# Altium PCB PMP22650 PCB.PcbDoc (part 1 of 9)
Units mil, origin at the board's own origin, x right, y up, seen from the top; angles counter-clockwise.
Board outline 11311 x 5233 mil, 8 copper layers (Layer 1, Layer 2, Layer 3, Layer 4, Layer 5, Layer 6, Layer 7, Layer 8), stack 88.6 mil thick; 633 components, 410 nets, 2503 pads, 1993 vias.
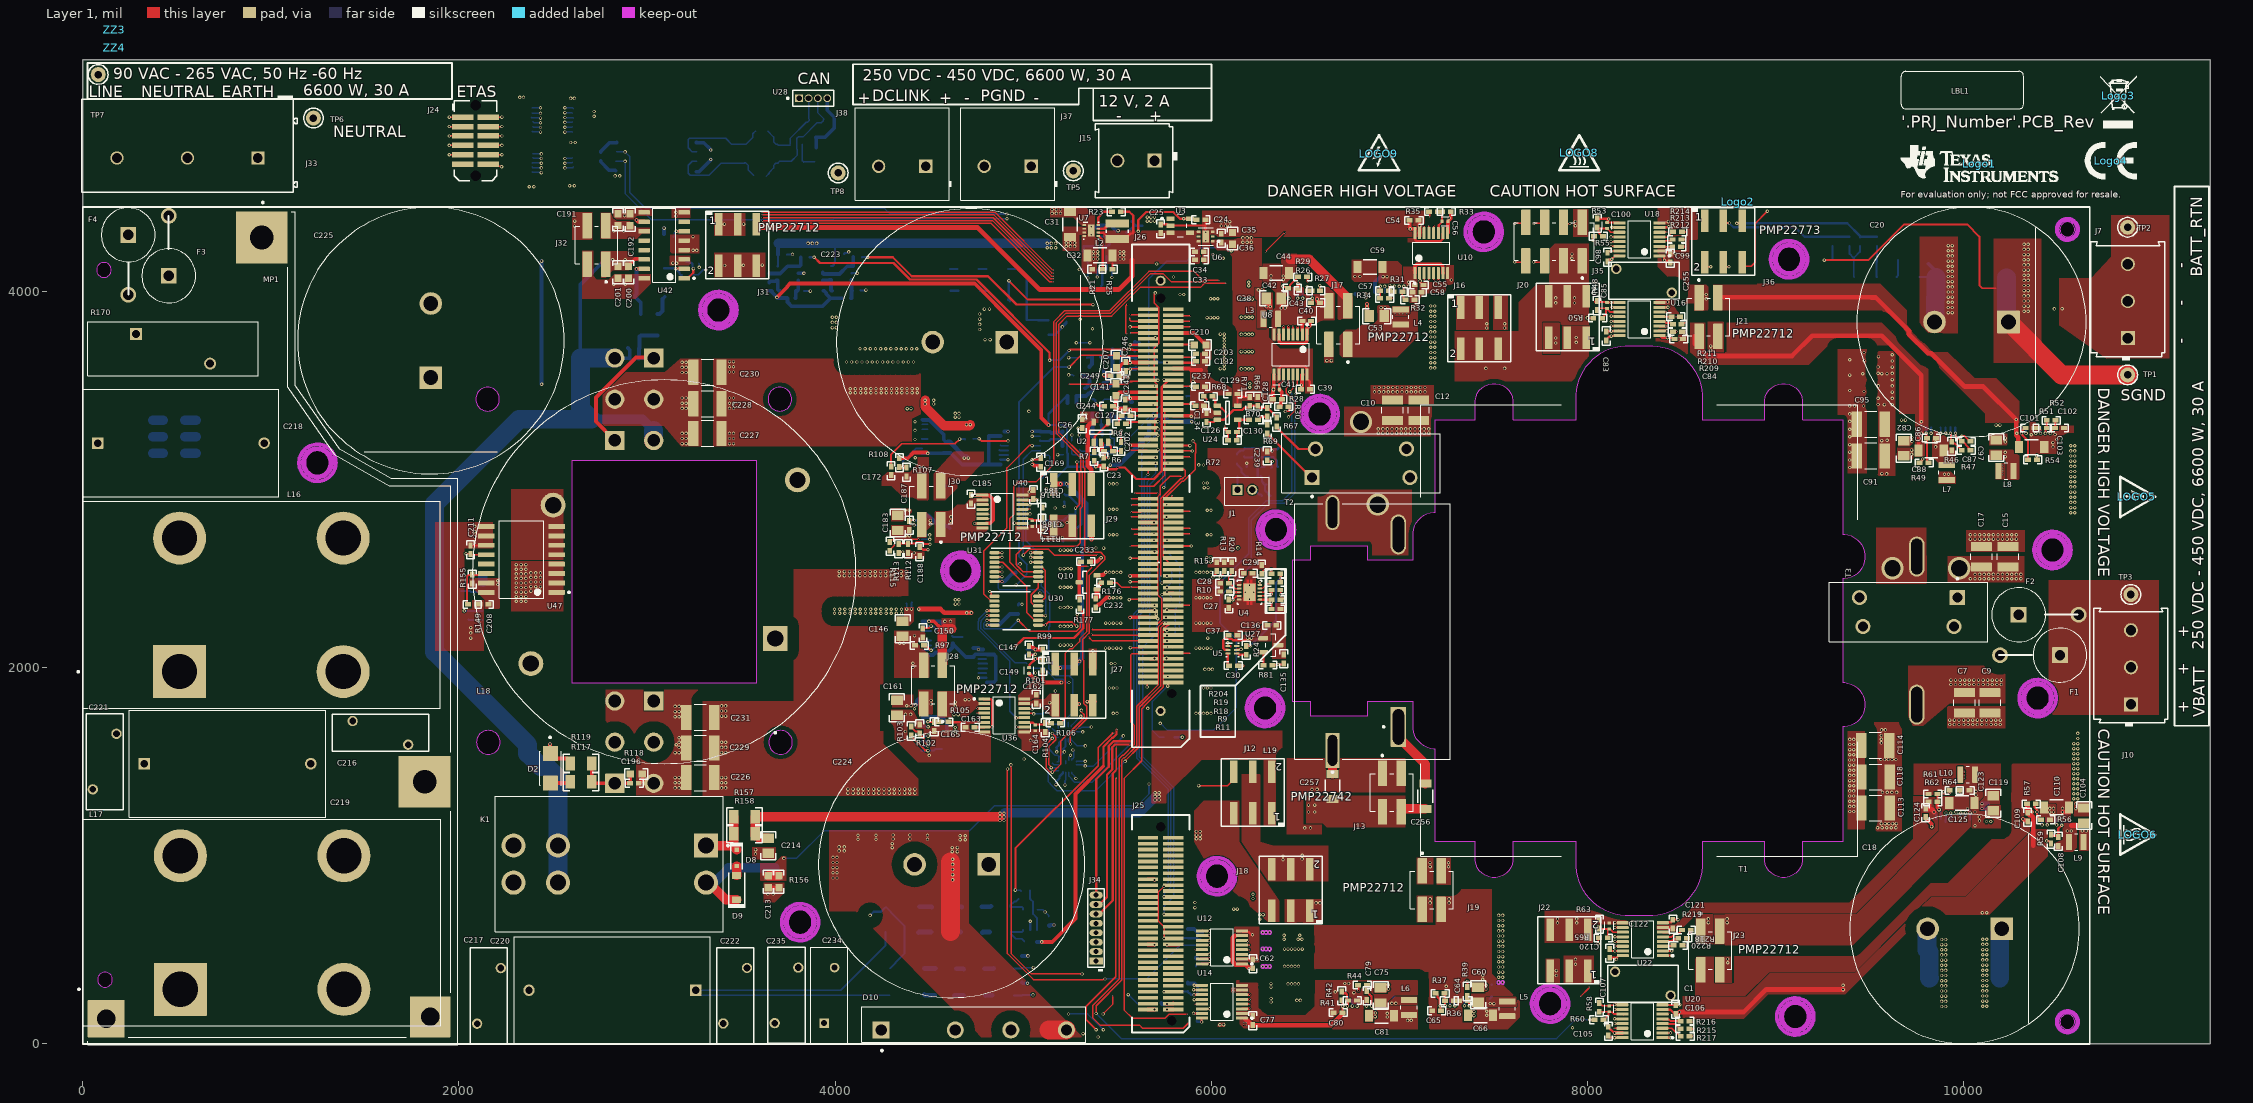
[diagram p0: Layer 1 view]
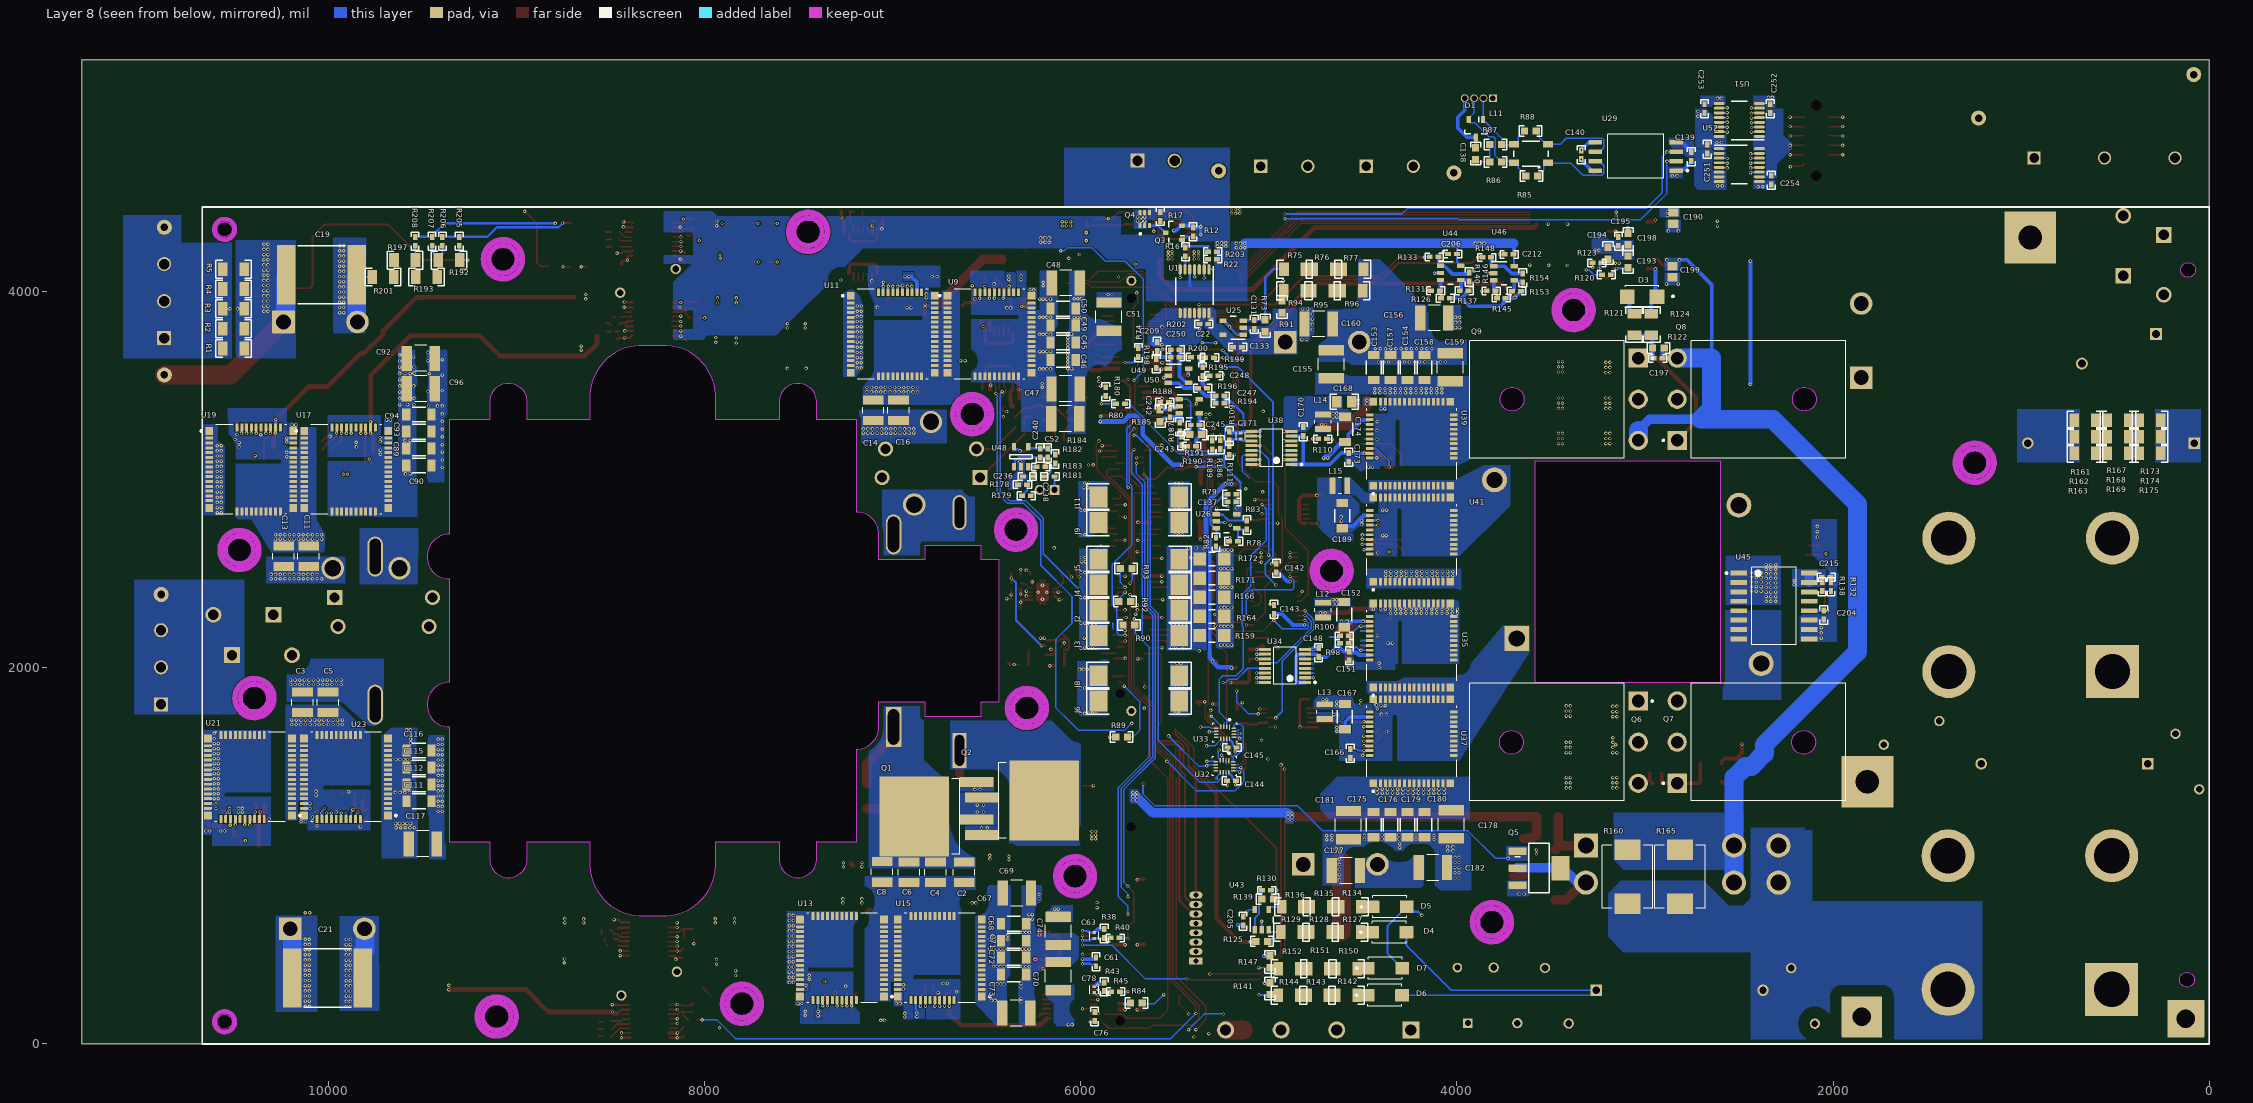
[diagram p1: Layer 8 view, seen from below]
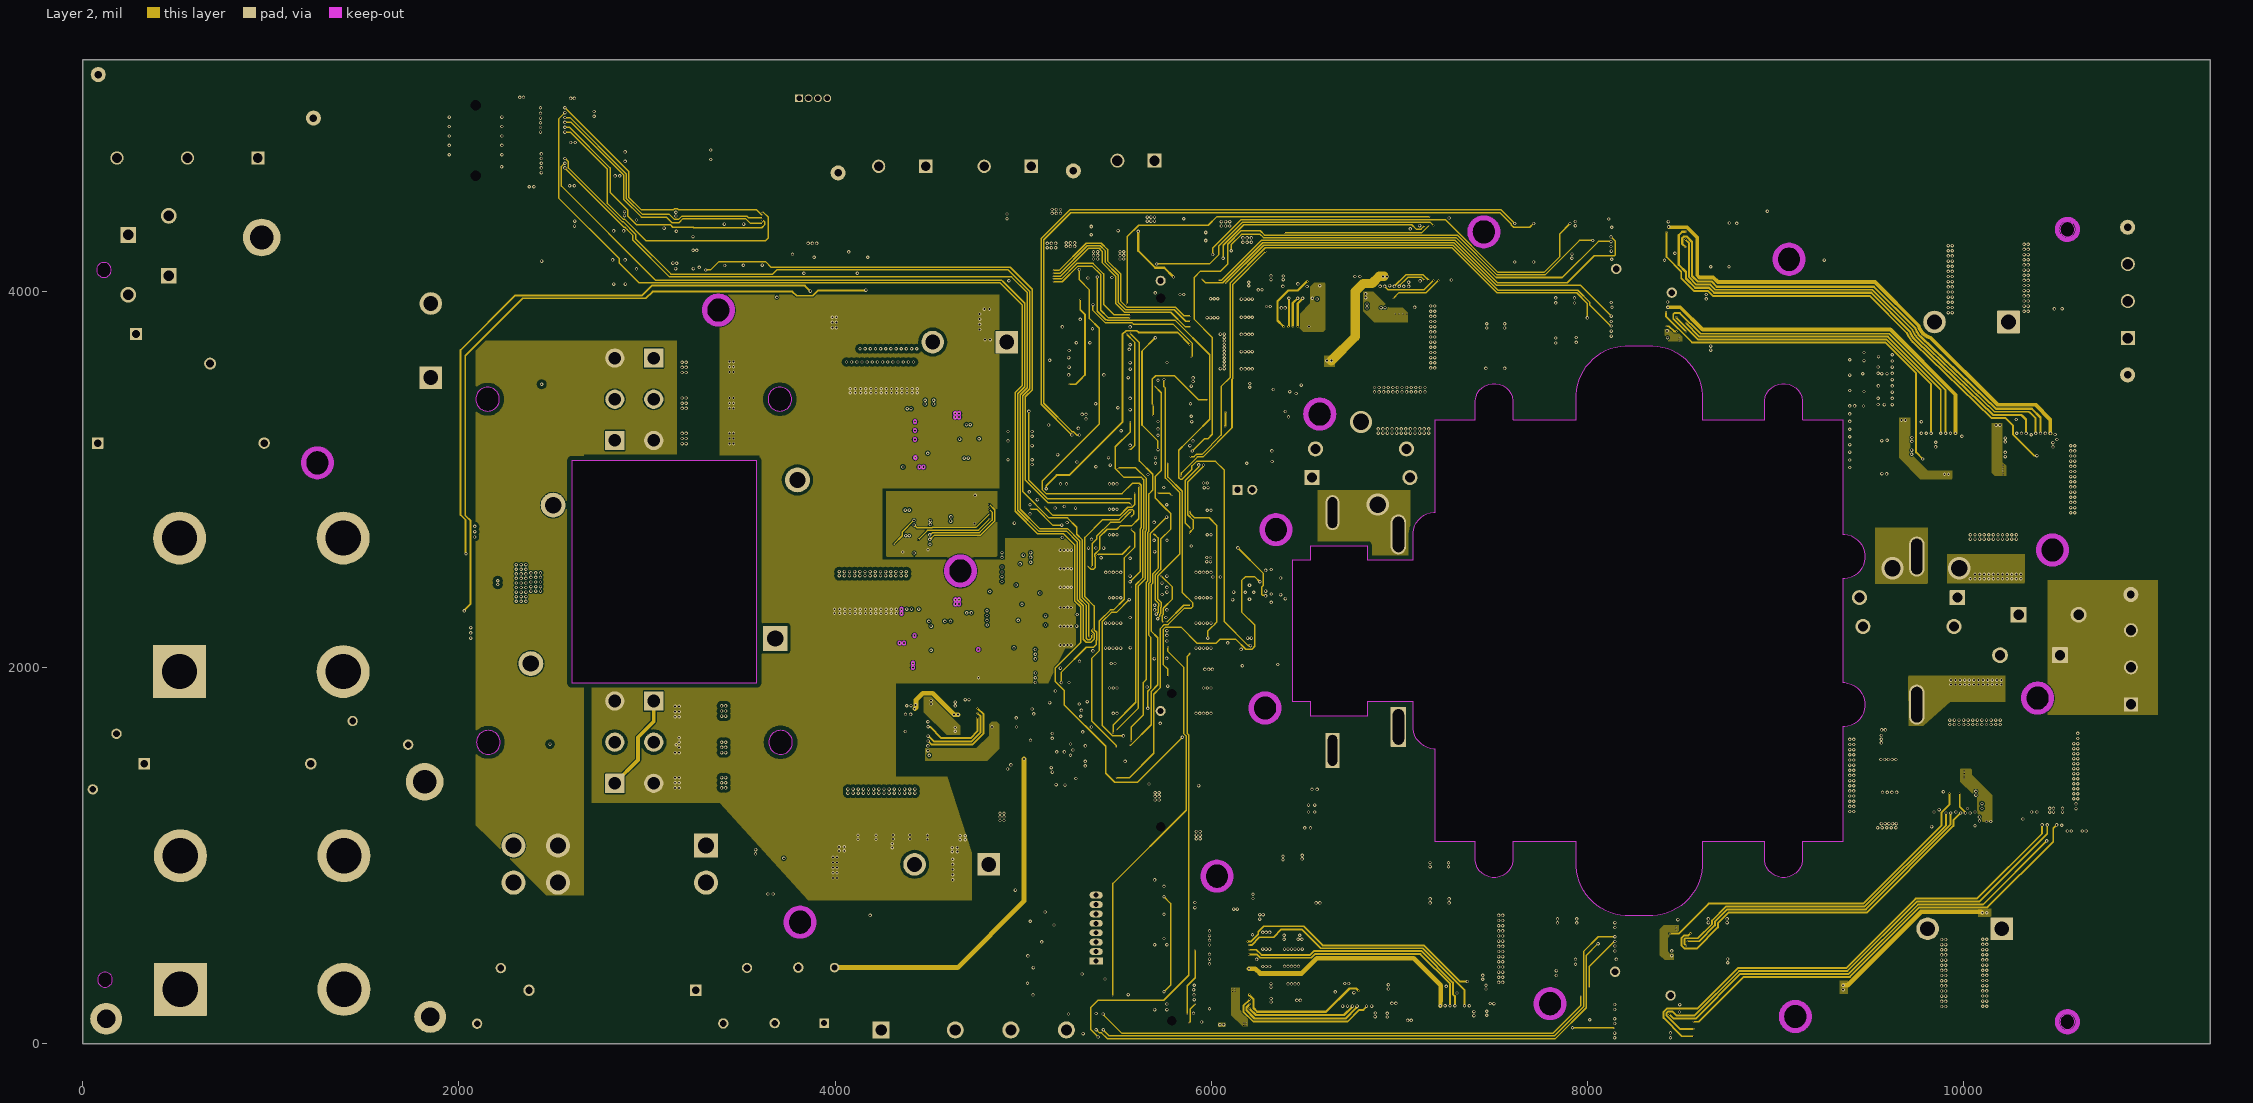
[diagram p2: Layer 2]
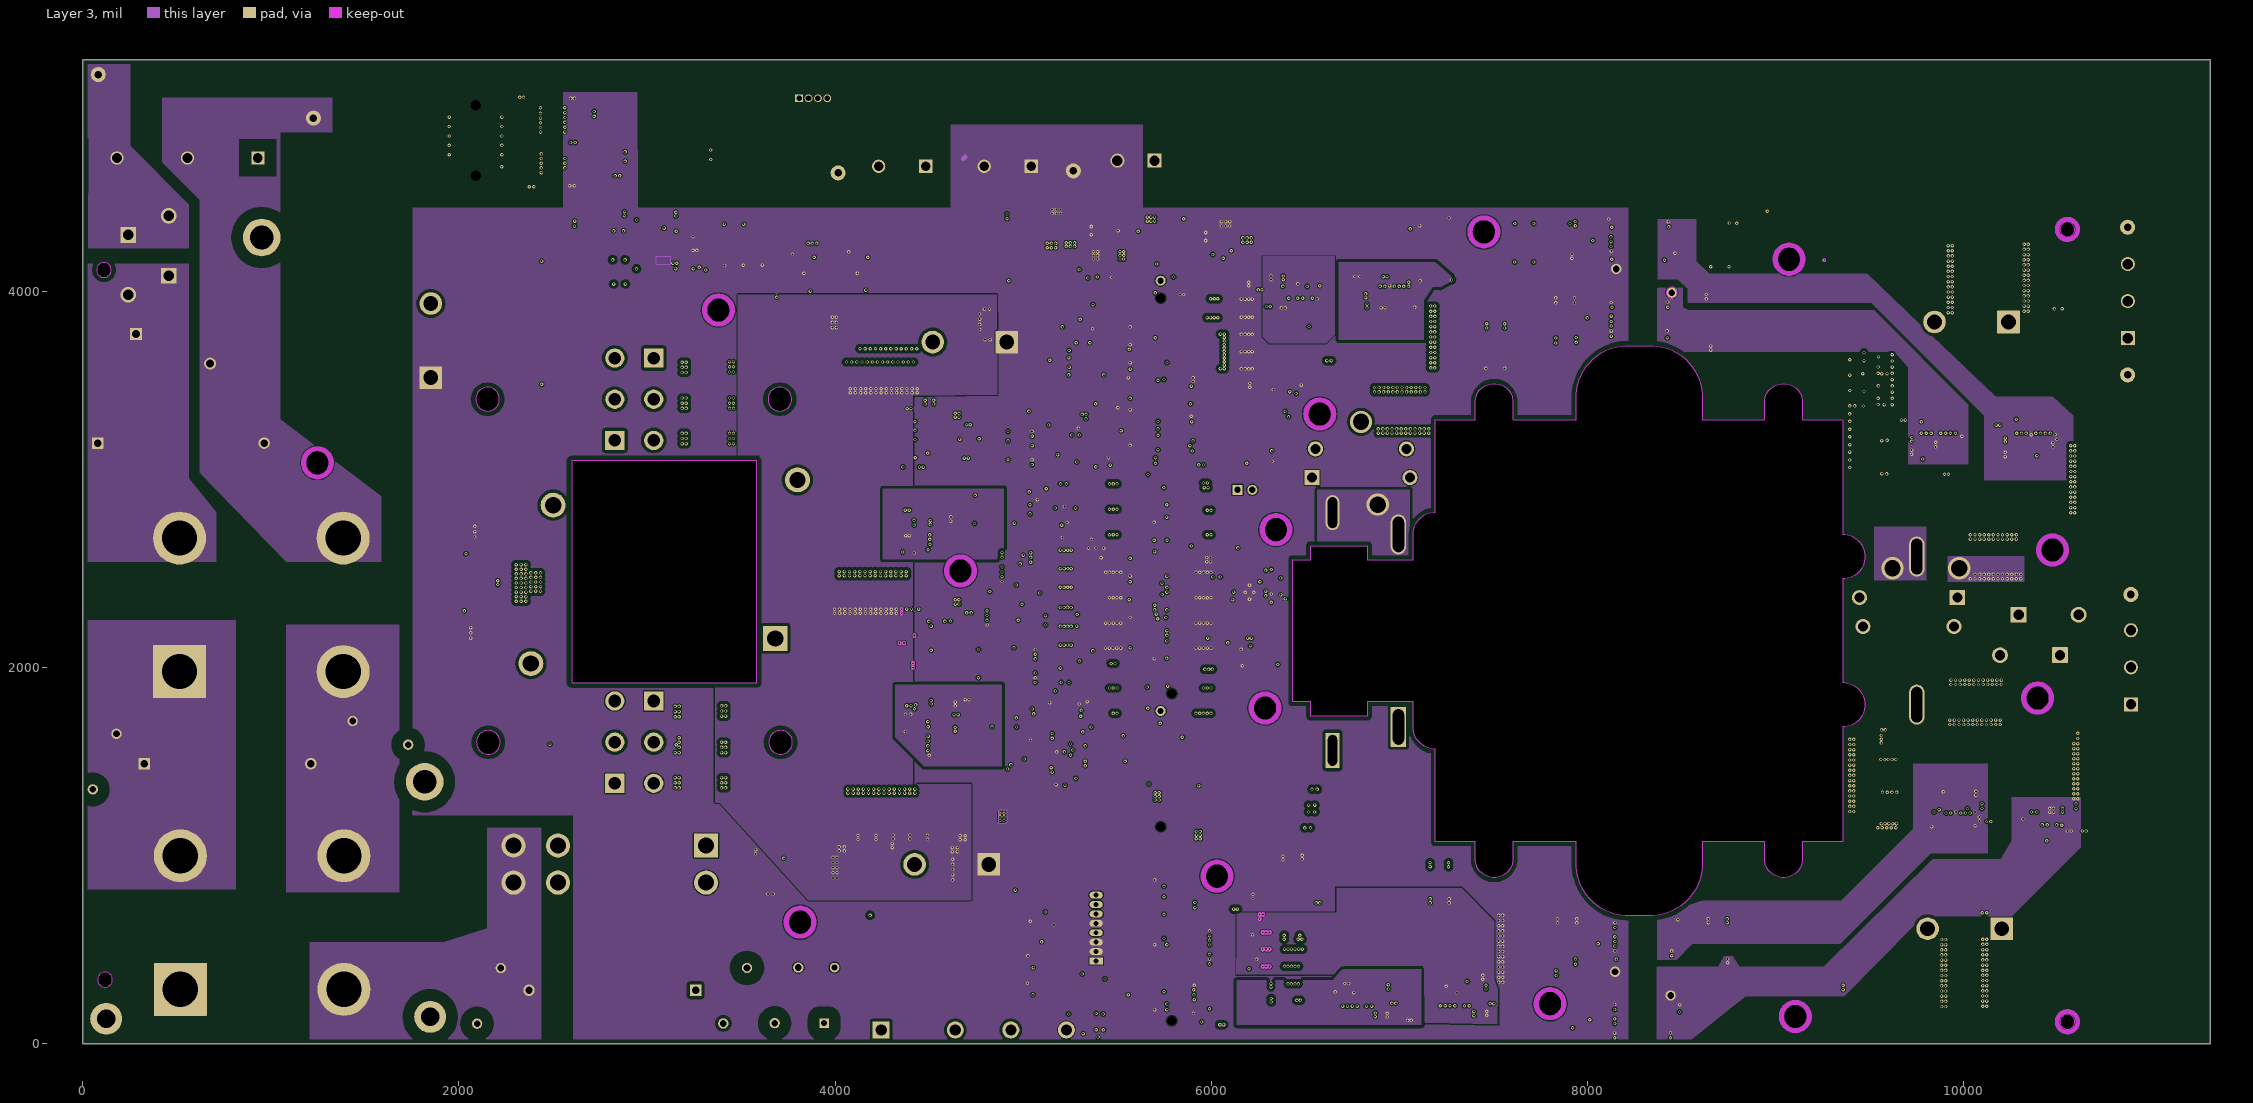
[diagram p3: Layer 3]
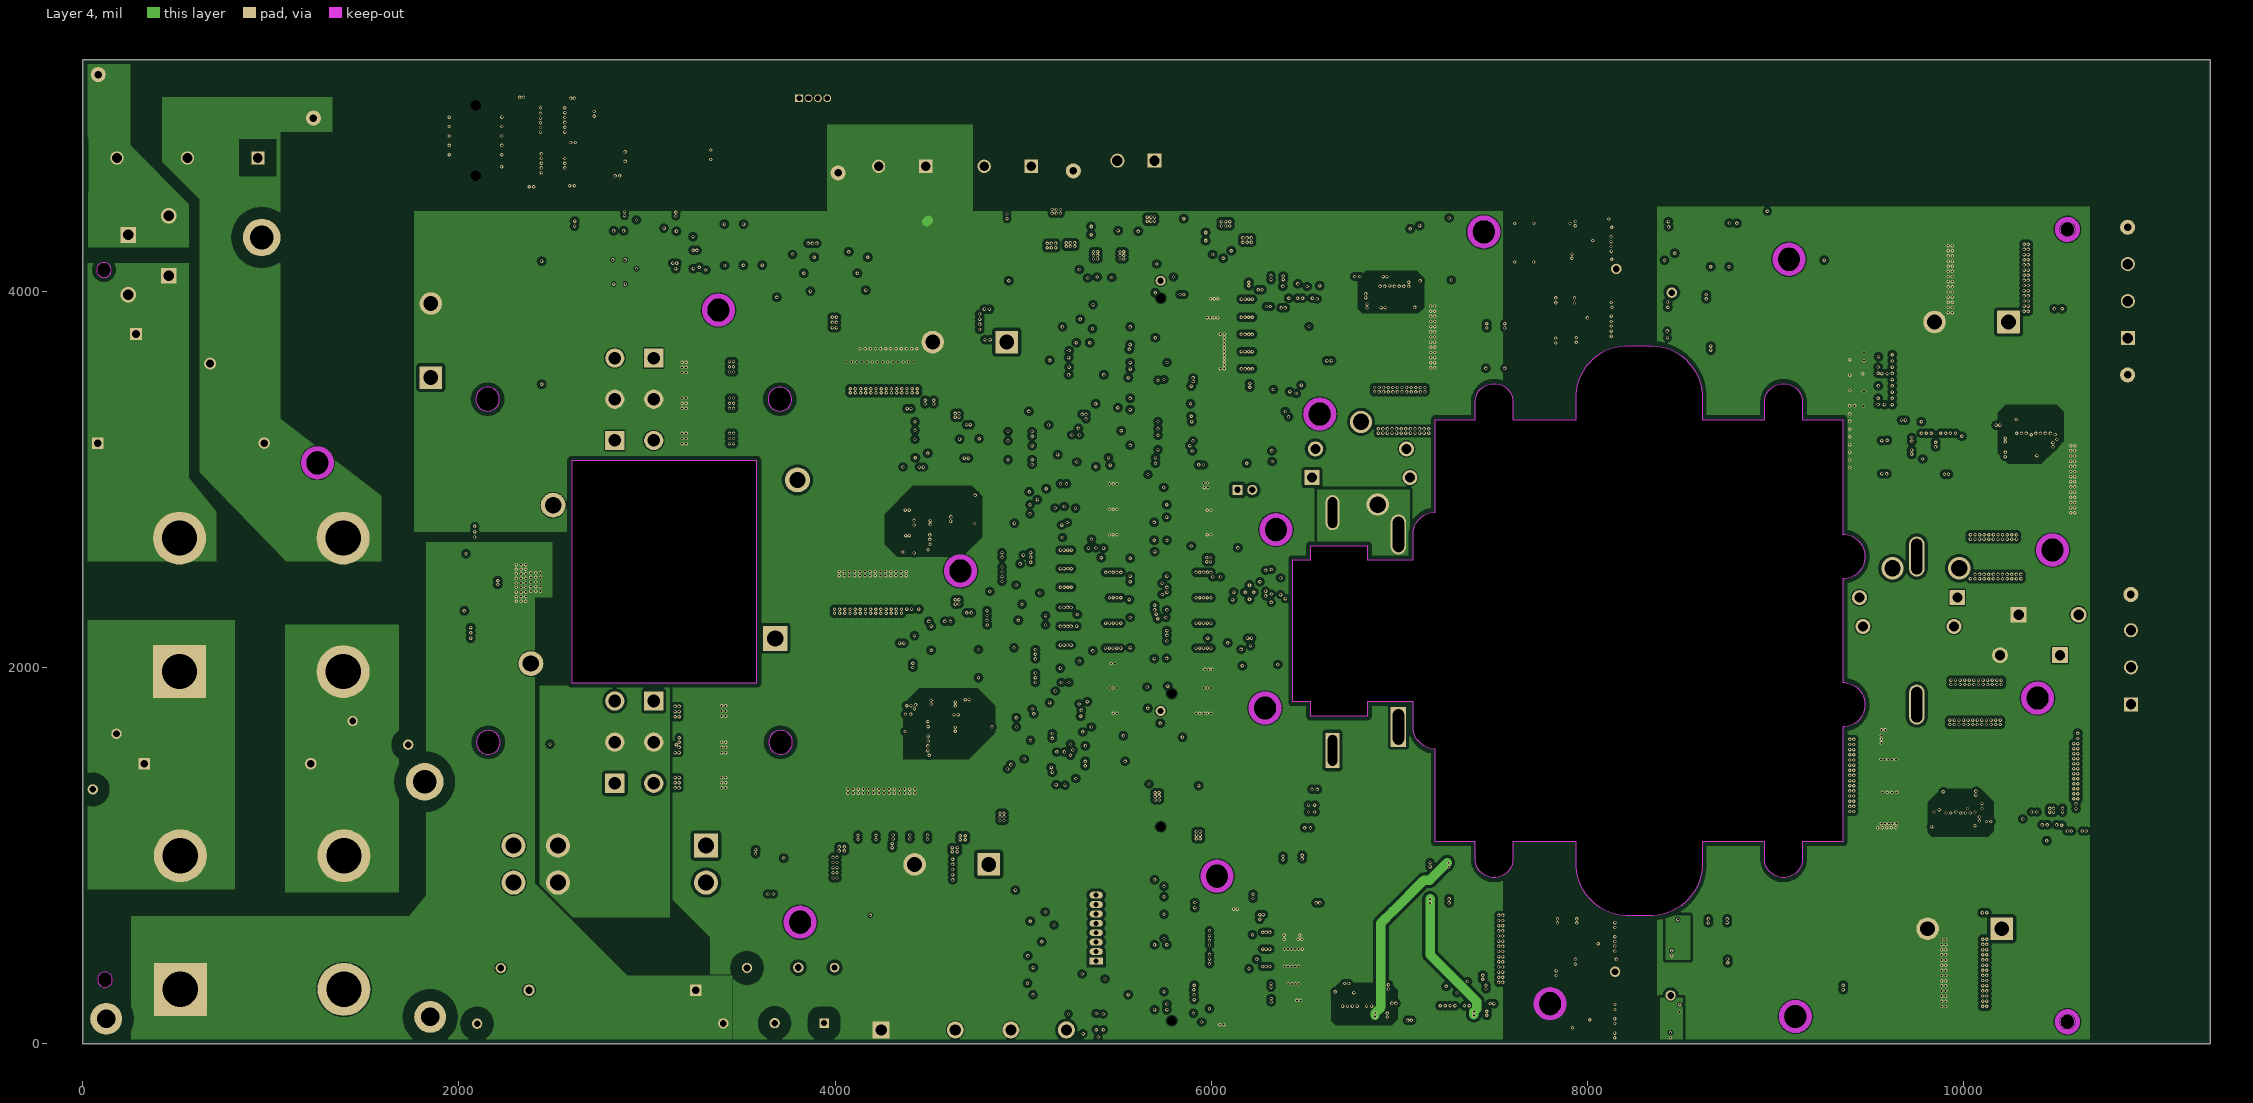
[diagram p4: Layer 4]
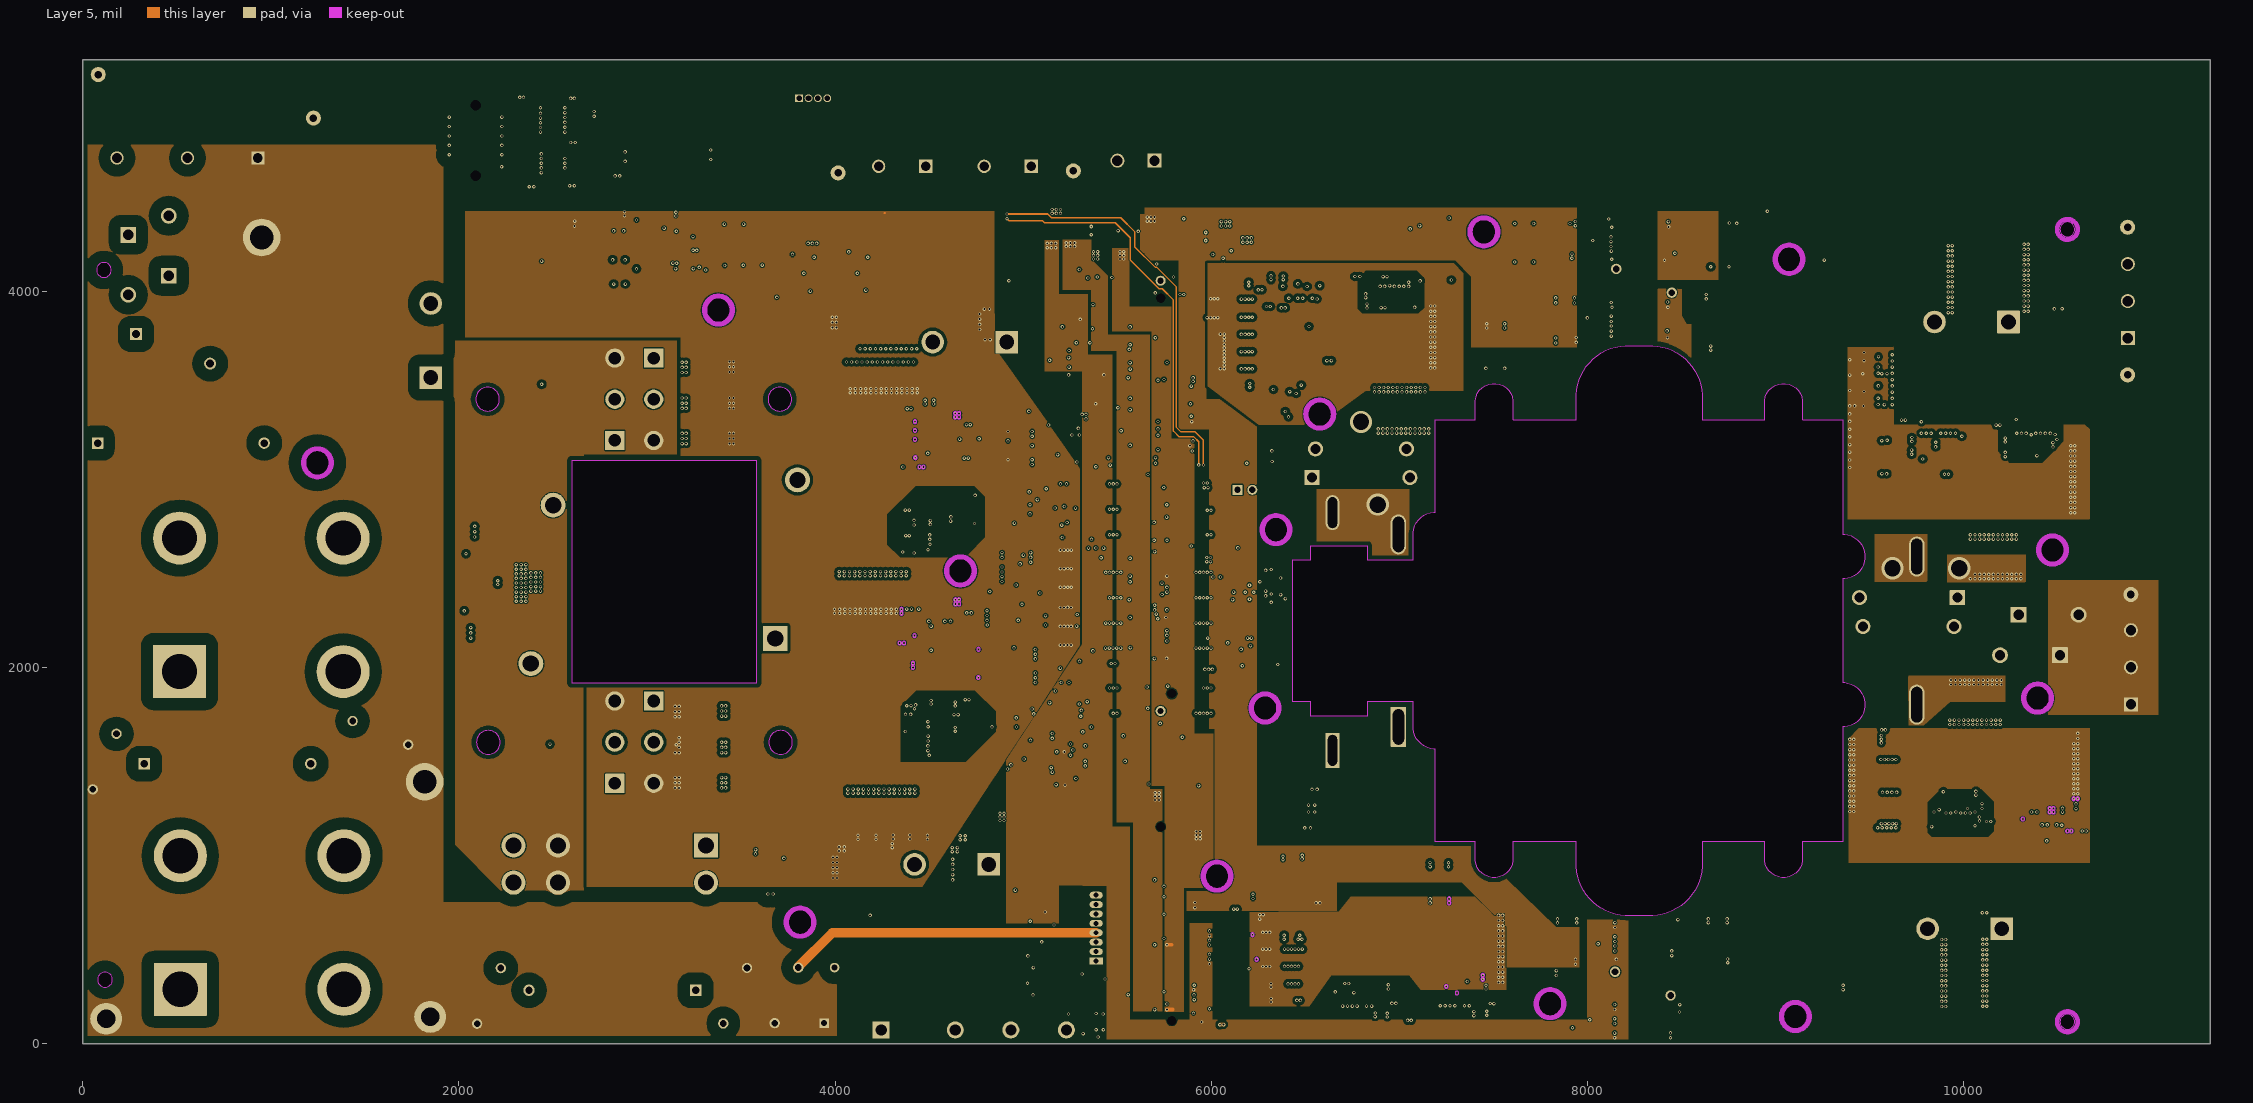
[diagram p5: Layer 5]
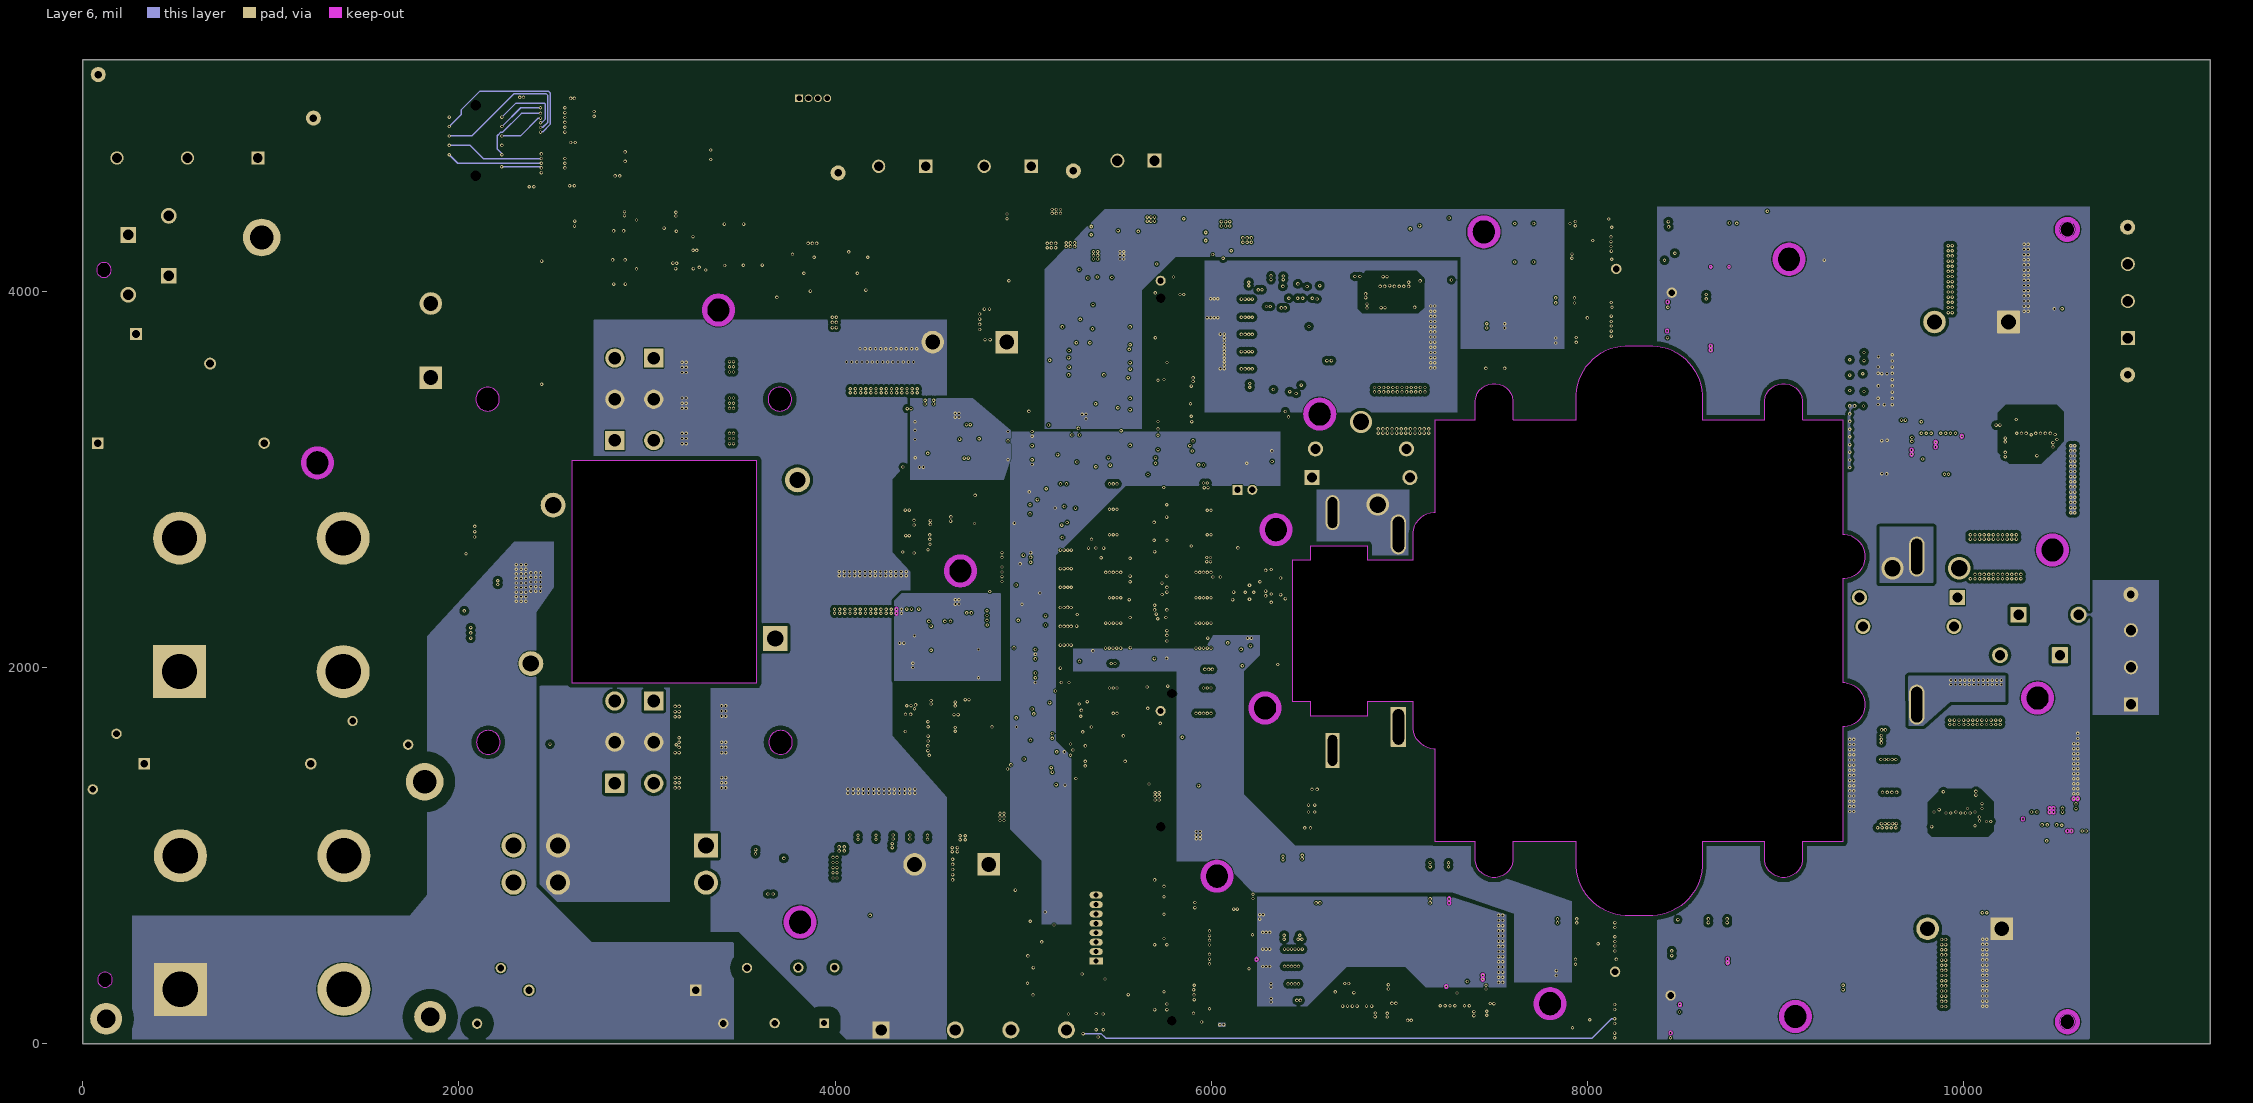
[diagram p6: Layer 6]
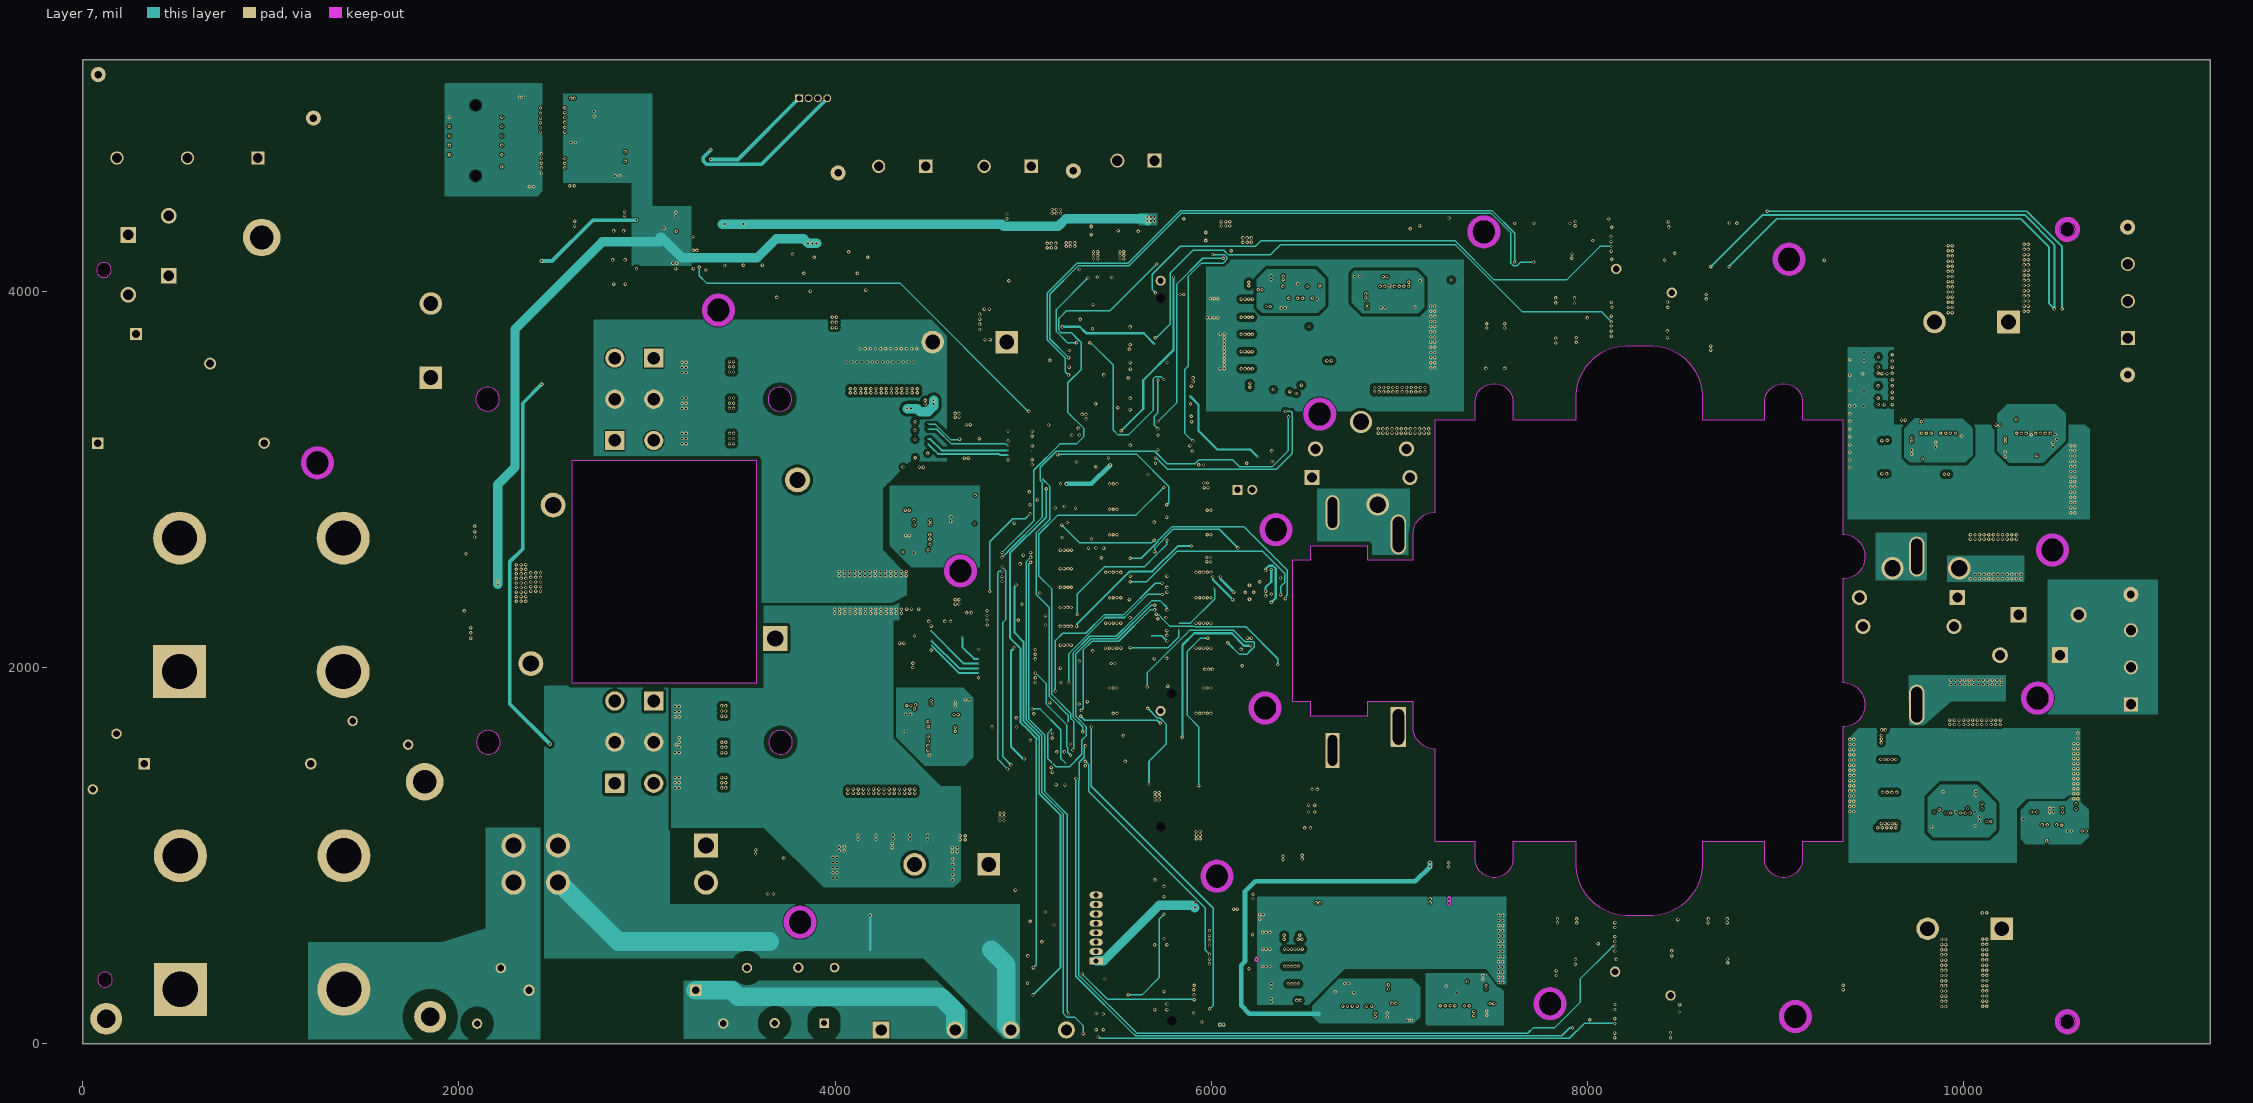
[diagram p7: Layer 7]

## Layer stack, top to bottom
Top Solder: solder mask 0.4, Solder Resist, Dk 3.5
Layer 1: signal copper 2.4
Dielectric 1: core 2.8, FR-4, Dk 4.1
Layer 2: signal copper 1.2
Dielectric 2: prepreg 8, FR-4, Dk 4.1
Layer 3: signal copper 2.4
Dielectric 3: core 9.6, FR-4, Dk 4.1
Layer 4: signal copper 2.4
Dielectric 4: prepreg 31, FR-4, Dk 4.1
Layer 5: signal copper 2.4
Dielectric 5: core 9.6, FR-4, Dk 4.1
Layer 6: signal copper 2.4
Dielectric 6: prepreg 8, FR-4, Dk 4.1
Layer 7: signal copper 1.2
Dielectric 7: core 2.8, FR-4, Dk 4.1
Layer 8: signal copper 2.4
Bottom Solder: solder mask 0.4, Solder Resist, Dk 3.5

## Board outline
0,0 11311,0 11311,5233 0,5233
cut-out: 4602.91,2514.99 ccw(c4665.9,2514.99) 4665.9,2452 ccw(c4665.9,2514.99) 4728.89,2514.99 ccw(c4665.9,2514.99) 4665.9,2577.98 ccw(c4665.9,2514.99)
cut-out: 3750.47,647.46 ccw(c3813.46,647.46) 3813.46,584.47 ccw(c3813.46,647.46) 3876.45,647.46 ccw(c3813.46,647.46) 3813.46,710.45 ccw(c3813.46,647.46)
cut-out: 3316.19,3901.84 ccw(c3379.18,3901.84) 3379.18,3838.85 ccw(c3379.18,3901.84) 3442.17,3901.84 ccw(c3379.18,3901.84) 3379.18,3964.83 ccw(c3379.18,3901.84)
cut-out: 1184.19,3089.84 ccw(c1247.18,3089.84) 1247.18,3026.85 ccw(c1247.18,3089.84) 1310.17,3089.84 ccw(c1247.18,3089.84) 1247.18,3152.83 ccw(c1247.18,3089.84)
cut-out: 10408.9,2626.17 ccw(c10471.89,2626.17) 10471.89,2563.18 ccw(c10471.89,2626.17) 10534.89,2626.17 ccw(c10471.89,2626.17) 10471.89,2689.16 ccw(c10471.89,2626.17)
cut-out: 3642.91,3427.99 ccw(c3705.9,3427.99) 3705.9,3365 ccw(c3705.9,3427.99) 3768.89,3427.99 ccw(c3705.9,3427.99) 3705.9,3490.98 ccw(c3705.9,3427.99)
cut-out: 2089.13,3427.99 ccw(c2152.12,3427.99) 2152.12,3365 ccw(c2152.12,3427.99) 2215.11,3427.99 ccw(c2152.12,3427.99) 2152.12,3490.98 ccw(c2152.12,3427.99)
cut-out: 2093.01,1603.71 ccw(c2156,1603.71) 2156,1540.72 ccw(c2156,1603.71) 2219,1603.71 ccw(c2156,1603.71) 2156,1666.7 ccw(c2156,1603.71)
cut-out: 3646.79,1603.71 ccw(c3709.78,1603.71) 3709.78,1540.72 ccw(c3709.78,1603.71) 3772.77,1603.71 ccw(c3709.78,1603.71) 3709.78,1666.7 ccw(c3709.78,1603.71)
cut-out: 7385.58,4317.63 ccw(c7448.57,4317.63) 7448.57,4254.63 ccw(c7448.57,4317.63) 7511.56,4317.63 ccw(c7448.57,4317.63) 7448.57,4380.62 ccw(c7448.57,4317.63)
cut-out: 9041.8,145.99 ccw(c9104.8,145.99) 9104.8,83 ccw(c9104.8,145.99) 9167.79,145.99 ccw(c9104.8,145.99) 9104.8,208.98 ccw(c9104.8,145.99)
cut-out: 10511.81,118.11 ccw(c10551.18,118.11) 10551.18,78.74 ccw(c10551.18,118.11) 10590.55,118.11 ccw(c10551.18,118.11) 10551.18,157.48 ccw(c10551.18,118.11)
cut-out: 6222.58,1786.37 ccw(c6285.57,1786.37) 6285.57,1723.38 ccw(c6285.57,1786.37) 6348.56,1786.37 ccw(c6285.57,1786.37) 6285.57,1849.37 ccw(c6285.57,1786.37)
cut-out: 10511.81,4330.71 ccw(c10551.18,4330.71) 10551.18,4291.34 ccw(c10551.18,4330.71) 10590.55,4330.71 ccw(c10551.18,4330.71) 10551.18,4370.08 ccw(c10551.18,4330.71)
cut-out: 5966.85,891.93 ccw(c6029.84,891.93) 6029.84,828.94 ccw(c6029.84,891.93) 6092.84,891.93 ccw(c6029.84,891.93) 6029.84,954.92 ccw(c6029.84,891.93)
cut-out: 6280.44,2734.37 ccw(c6343.43,2734.37) 6343.43,2671.38 ccw(c6343.43,2734.37) 6406.42,2734.37 ccw(c6343.43,2734.37) 6343.43,2797.37 ccw(c6343.43,2734.37)
cut-out: 78.74,341.68 ccw(c118.11,341.68) 118.11,302.31 ccw(c118.11,341.68) 157.48,341.68 ccw(c118.11,341.68) 118.11,381.05 ccw(c118.11,341.68)
cut-out: 73,4115.06 ccw(c112.37,4115.06) 112.37,4075.69 ccw(c112.37,4115.06) 151.74,4115.06 ccw(c112.37,4115.06) 112.37,4154.43 ccw(c112.37,4115.06)
cut-out: 6513.2,3348.75 ccw(c6576.2,3348.75) 6576.2,3285.76 ccw(c6576.2,3348.75) 6639.19,3348.75 ccw(c6576.2,3348.75) 6576.2,3411.75 ccw(c6576.2,3348.75)
cut-out: 7737.73,214.14 ccw(c7800.73,214.14) 7800.73,151.15 ccw(c7800.73,214.14) 7863.72,214.14 ccw(c7800.73,214.14) 7800.73,277.13 ccw(c7800.73,214.14)
cut-out: 10329.8,1838.99 ccw(c10392.8,1838.99) 10392.8,1776 ccw(c10392.8,1838.99) 10455.79,1838.99 ccw(c10392.8,1838.99) 10392.8,1901.98 ccw(c10392.8,1838.99)
cut-out: 9008.28,4171.97 ccw(c9071.27,4171.97) 9071.27,4108.98 ccw(c9071.27,4171.97) 9134.26,4171.97 ccw(c9071.27,4171.97) 9071.27,4234.97 ccw(c9071.27,4171.97)
cut-out: 7191.59,1075.55 7191.59,1567.68 7182.3,1567.68 7163.93,1570.59 7146.25,1576.33 7129.69,1584.77 7114.65,1595.7 7101.5,1608.84 7090.57,1623.88 7082.13,1640.45 7076.39,1658.13 7073.48,1676.49 7073.48,1820 6829.31,1820 6829.31,1743.44 6527.25,1743.44 6527.25,1820 6433.35,1820 6433.35,2574 6527.25,2574 6527.25,2648.6 6829.31,2648.6 6829.31,2574 7073.48,2574 7073.48,2718.7 7076.39,2737.07 7082.13,2754.75 7090.57,2771.31 7101.5,2786.35 7114.65,2799.5 7129.69,2810.43 7146.25,2818.87 7163.93,2824.61 7182.3,2827.52 7191.59,2827.52 7191.59,3319.65 7402,3319.65 7403.27,3320.04 7403.27,3420.89 7407.11,3440.21 7414.65,3458.41 7425.59,3474.79 7439.52,3488.72 7455.9,3499.66 7474.1,3507.2 7493.42,3511.04 7513.12,3511.04 7532.44,3507.2 7550.64,3499.66 7567.01,3488.72 7580.94,3474.79 7591.89,3458.41 7599.42,3440.21 7603.27,3420.89 7603.27,3320.14 7604,3319.65 7939.62,3319.65 7939.62,3451.29 7942.28,3478.24 7947.56,3504.8 7955.42,3530.71 7965.78,3555.73 7978.55,3579.61 7993.59,3602.12 8010.77,3623.05 8029.91,3642.2 8050.85,3659.38 8073.36,3674.42 8097.24,3687.19 8122.26,3697.55 8148.17,3705.41 8174.73,3710.69 8201.67,3713.35 8215.21,3713.35 8333.32,3713.35 8346.86,3713.35 8373.81,3710.69 8400.37,3705.41 8426.28,3697.55 8451.3,3687.19 8475.18,3674.42 8497.69,3659.38 8518.62,3642.2 8537.77,3623.05 8554.95,3602.12 8569.99,3579.61 8582.75,3555.73 8593.12,3530.71 8600.98,3504.8 8606.26,3478.24 8608.91,3451.29 8608.91,3437.76 8608.91,3319.65 8942,3319.65 8942.12,3320.04 8942.12,3420.89 8945.96,3440.21 8953.5,3458.41 8964.45,3474.79 8978.37,3488.72 8994.75,3499.66 9012.95,3507.2 9032.27,3511.04 9051.97,3511.04 9071.29,3507.2 9089.49,3499.66 9105.87,3488.72 9119.8,3474.79 9130.74,3458.41 9138.28,3440.21 9142.12,3420.89 9142.12,3320.14 9143,3319.65 9356.94,3319.65 9356.94,2709.41 9366.24,2709.41 9384.6,2706.5 9402.28,2700.76 9418.85,2692.32 9433.89,2681.39 9447.03,2668.24 9457.96,2653.2 9466.4,2636.64 9472.15,2618.96 9475.06,2600.59 9475.06,2582 9472.15,2563.64 9466.4,2545.96 9457.96,2529.4 9447.03,2514.36 9433.89,2501.21 9418.85,2490.28 9402.28,2481.84 9384.6,2476.1 9366.24,2473.19 9356.94,2473.19 9356.94,1922.01 9366.24,1922.01 9384.6,1919.1 9402.28,1913.35 9418.85,1904.91 9433.89,1893.99 9447.03,1880.84 9457.96,1865.8 9466.4,1849.24 9472.15,1831.56 9475.06,1813.19 9475.06,1794.6 9472.15,1776.24 9466.4,1758.56 9457.96,1741.99 9447.03,1726.95 9433.89,1713.81 9418.85,1702.88 9402.28,1694.44 9384.6,1688.7 9366.24,1685.79 9356.94,1685.79 9356.94,1075.55 9142.12,1075.55 9142.12,975.02 9138.28,955.7 9130.74,937.5 9119.8,921.12 9105.87,907.19 9089.49,896.25 9071.29,888.71 9051.97,884.87 9032.27,884.87 9012.95,888.71 8994.75,896.25 8978.37,907.19 8964.45,921.12 8953.5,937.5 8945.96,955.7 8942.12,975.02 8942.12,1075.55 8608.91,1075.55 8608.91,957.44 8608.91,943.9 8606.26,916.95 8600.98,890.4 8593.12,864.49 8582.75,839.47 8569.99,815.59 8554.95,793.07 8537.77,772.14 8518.62,753 8497.69,735.82 8475.18,720.77 8451.3,708.01 8426.28,697.65 8400.37,689.79 8373.81,684.5 8346.86,681.85 8201.67,681.85 8174.73,684.5 8148.17,689.79 8122.26,697.65 8097.24,708.01 8073.36,720.77 8050.85,735.82 8029.91,753 8010.77,772.14 7993.59,793.07 7978.55,815.59 7965.78,839.47 7955.42,864.49 7947.56,890.4 7942.28,916.95 7939.62,943.9 7939.62,1075.55 7603.27,1075.55 7603.27,975.02 7599.42,955.7 7591.89,937.5 7580.94,921.12 7567.01,907.19 7550.64,896.25 7532.44,888.71 7513.12,884.87 7493.42,884.87 7474.1,888.71 7455.9,896.25 7439.52,907.19 7425.59,921.12 7414.65,937.5 7407.11,955.7 7403.27,975.02 7403.27,1075.55
cut-out: 2598.8,1920.05 3583.06,1920.05 3583.06,3101.15 2598.8,3101.15

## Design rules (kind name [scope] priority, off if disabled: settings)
AcuteAngle [All] p1: minimum=4.50000000000000E+0001 checktracksonly=FALSE
AssemblyTestPointUsage [All] p1: valid=2
BoardOutlineClearance BoardOutlineClearance_Silk [(OnLayer('Top Overlay') or OnLayer('Bottom Overlay') or OnTopSilkscreen or OnBottomSilkscreen)] p1: gap=0 ignorepadtopadclearanceinfootprint=FALSE
BoardOutlineClearance BoardOutlineClearance_MountingHoles [OnCopper and InComponentClass('Mounting Holes')] p2: gap=39.37 ignorepadtopadclearanceinfootprint=FALSE
BoardOutlineClearance BoardOutlineClearance_Poly [OnCopper and IsPoly] p3: gap=25 ignorepadtopadclearanceinfootprint=FALSE
BoardOutlineClearance [OnCopper And Not InComponentClass('Logo') and not InComponentClass('FiducialMark') and not InRegion(1000,500,4000,800)] p4: gap=25 ignorepadtopadclearanceinfootprint=FALSE
Clearance Clearance_Earth_Outside [(OnLayer('Layer 1') Or OnLayer('Layer 8')) And InNet('EARTH')] p1: gap=162.99 ignorepadtopadclearanceinfootprint=TRUE
Clearance Clearance_Earth_Inside [InNet('EARTH')] p2: gap=62.99 ignorepadtopadclearanceinfootprint=TRUE
Clearance Clearance_HV_Outside [InNetClass('HV') And (OnTopLayer Or OnBottomLayer Or IsVia Or IsPad) And (Not Keepout) And InAnyNet vs (Not InNetClass('HV')) And (OnTopLayer Or OnBottomLayer Or IsVia Or IsPad) And (Not Keepout) And InAnyNet] p3: gap=60 ignorepadtopadclearanceinfootprint=TRUE
Clearance Clearance_HV_Inside [InNetClass('HV') vs Not InNetClass('HV') And InAnyNet] p4: gap=16 ignorepadtopadclearanceinfootprint=TRUE
Clearance Clearance_HV_SW_Outside [InNetClass('HV_SW') And (OnTopLayer Or OnBottomLayer Or IsVia Or IsPad) And (Not Keepout) And InAnyNet vs (Not InNetClass('HV_SW')) And (OnTopLayer Or OnBottomLayer Or IsVia Or IsPad) And (Not Keepout) And InAnyNet] p5: gap=60 ignorepadtopadclearanceinfootprint=TRUE
Clearance Clearance_HV_SW_Inside [InNetClass('HV_SW') vs Not InNetClass('HV_SW') And InAnyNet] p6: gap=16 ignorepadtopadclearanceinfootprint=TRUE
Clearance Clearance_Keepouts [((IsTrack Or IsArc) And Not InPoly) And IsFree and IsKeepOut vs ((IsTrack Or IsArc) And Not InPoly) And IsFree and IsKeepOut] p7: gap=0 ignorepadtopadclearanceinfootprint=FALSE
Clearance Clearance_Poly [InPolygon] p8: gap=5.5 ignorepadtopadclearanceinfootprint=TRUE except(5.51: Arc-Hole Track-Hole SMDPad-Hole THPad-Hole Via-Hole Fill-Hole Poly-Hole Region-Hole Text-Hole)
Clearance Clearance_FiducialMark [IsKeepOut and InComponentClass('FiducialMark') vs IsPad and InComponentClass('FiducialMark')] p9: gap=0 ignorepadtopadclearanceinfootprint=FALSE
Clearance [All] p10: gap=5.5 ignorepadtopadclearanceinfootprint=TRUE except(5: THPad-THPad)
ComponentClearance PFC_Inductor [InComponent('L18')] p1: gap=0 collisioncheckmode=3 verticalgap=10 showdistances=FALSE
ComponentClearance LC_Ind_XFMR [InComponent('T1') vs InComponent('L19')] p2: gap=0 collisioncheckmode=3 verticalgap=0 showdistances=FALSE
ComponentClearance LMG_Bottom_Clearance [HasFootprint('RQS0052A-MFG') vs Not HasFootprint('RQS0052A-MFG')] p3: gap=78.74 collisioncheckmode=3 verticalgap=0 showdistances=FALSE
ComponentClearance ComponentClearance_Sec_RogCoil [InComponent('T1') vs InComponent('T3')] p4: gap=0 collisioncheckmode=3 verticalgap=0 showdistances=FALSE
ComponentClearance ComponentClearance_MountingHoles_FiducialMarks [InComponentClass('Mounting Holes') vs InComponentClass('FiducialMark')] p5: gap=50 collisioncheckmode=3 verticalgap=10 showdistances=FALSE
ComponentClearance ComponentClearance_Shunt [InComponentClass('Header') vs InComponentClass('Shunt')] p6: gap=0 collisioncheckmode=3 verticalgap=0 showdistances=FALSE
ComponentClearance ComponentClearance_Logo [InComponentClass('Logo')] p7: gap=50 collisioncheckmode=3 verticalgap=10 showdistances=FALSE
ComponentClearance ComponentClearance_ScrewToNut [(HasFootprint('NY PMS 440 0025 PH')) vs (HasFootprint('Keystone_1902C'))] p8: gap=5 collisioncheckmode=3 verticalgap=10 showdistances=FALSE
ComponentClearance ComponentClearance_MountingHoles [InComponentClass('Mounting Holes')] p9: gap=250 collisioncheckmode=3 verticalgap=100000 showdistances=FALSE
ComponentClearance ComponentClearance_SmallPassives [HasFootprint('0201*') or HasFootprint('0402*') or HasFootprint('0508') or HasFootprint('0603*') or HasFootprint('0612') or HasFootprint('0805*') or HasFootprint('0815*') or HasFootprint('0830*') or HasFootprint('1206*') or HasFootprint('1210*') or HasFootprint('1808*') or HasFootprint('1812*') or HasFootprint('1825*') or HasFootprint('2010*') or HasFootprint('2220*') or HasFootprint('2225*') or HasFootprint('2512*') or HasFootprint('2728*') or HasFootprint('3518*') vs HasFootprint('0201*') or HasFootprint('0402*') or HasFootprint('0508') or HasFootprint('0603*') or HasFootprint('0612') or HasFootprint('0805*') or HasFootprint('0815*') or HasFootprint('0830*') or HasFootprint('1206*') or HasFootprint('1210*') or HasFootprint('1808*') or HasFootprint('1812*') or HasFootprint('1825*') or HasFootprint('2010*') or HasFootprint('2220*') or HasFootprint('2225*') or HasFootprint('2512*') or HasFootprint('2728*') or HasFootprint('3518*')] p10: gap=14.96 collisioncheckmode=3 verticalgap=10 showdistances=FALSE
ComponentClearance ComponentClearance_THtoSMT [IsThruComponent vs IsSMTComponent] p11: gap=40 collisioncheckmode=3 verticalgap=30 showdistances=FALSE
ComponentClearance ComponentClearance_THtoTH [IsThruComponent vs IsThruComponent] p12: gap=30 collisioncheckmode=3 verticalgap=30 showdistances=FALSE
ComponentClearance [All] p13: gap=30 collisioncheckmode=3 verticalgap=10 showdistances=FALSE
DiffPairsRouting [All] p1: maxlimit=100 minlimit=10 mostfreqgap=10 toplayer_minwidth=15 toplayer_maxwidth=15 toplayer_prefwidth=15 midlayer1_minwidth=15 midlayer1_maxwidth=15 midlayer1_prefwidth=15 midlayer2_minwidth=15 midlayer2_maxwidth=15 midlayer2_prefwidth=15 midlayer3_minwidth=15 midlayer3_maxwidth=15 midlayer3_prefwidth=15 midlayer4_minwidth=15 midlayer4_maxwidth=15 midlayer4_prefwidth=15 midlayer5_minwidth=15 midlayer5_maxwidth=15 midlayer5_prefwidth=15 midlayer6_minwidth=15 midlayer6_maxwidth=15 midlayer6_prefwidth=15 bottomlayer_minwidth=15 bottomlayer_maxwidth=15 bottomlayer_prefwidth=15 substack1={36F540E3-592C-4459-9B98-FC5FBF0C6E90} toplayer_{36f540e3-592c-4459-9b98-fc5fbf0c6e90}_minwidth=15 toplayer_{36f540e3-592c-4459-9b98-fc5fbf0c6e90}_maxwidth=15 toplayer_{36f540e3-592c-4459-9b98-fc5fbf0c6e90}_prefwidth=15 midlayer1_{36f540e3-592c-4459-9b98-fc5fbf0c6e90}_minwidth=15 midlayer1_{36f540e3-592c-4459-9b98-fc5fbf0c6e90}_maxwidth=15 midlayer1_{36f540e3-592c-4459-9b98-fc5fbf0c6e90}_prefwidth=15 midlayer2_{36f540e3-592c-4459-9b98-fc5fbf0c6e90}_minwidth=15 midlayer2_{36f540e3-592c-4459-9b98-fc5fbf0c6e90}_maxwidth=15 midlayer2_{36f540e3-592c-4459-9b98-fc5fbf0c6e90}_prefwidth=15 midlayer3_{36f540e3-592c-4459-9b98-fc5fbf0c6e90}_minwidth=15 midlayer3_{36f540e3-592c-4459-9b98-fc5fbf0c6e90}_maxwidth=15 midlayer3_{36f540e3-592c-4459-9b98-fc5fbf0c6e90}_prefwidth=15 midlayer4_{36f540e3-592c-4459-9b98-fc5fbf0c6e90}_minwidth=15 midlayer4_{36f540e3-592c-4459-9b98-fc5fbf0c6e90}_maxwidth=15 midlayer4_{36f540e3-592c-4459-9b98-fc5fbf0c6e90}_prefwidth=15 midlayer5_{36f540e3-592c-4459-9b98-fc5fbf0c6e90}_minwidth=15 midlayer5_{36f540e3-592c-4459-9b98-fc5fbf0c6e90}_maxwidth=15 midlayer5_{36f540e3-592c-4459-9b98-fc5fbf0c6e90}_prefwidth=15 midlayer6_{36f540e3-592c-4459-9b98-fc5fbf0c6e90}_minwidth=15 midlayer6_{36f540e3-592c-4459-9b98-fc5fbf0c6e90}_maxwidth=15 midlayer6_{36f540e3-592c-4459-9b98-fc5fbf0c6e90}_prefwidth=15 bottomlayer_{36f540e3-592c-4459-9b98-fc5fbf0c6e90}_minwidth=15 bottomlayer_{36f540e3-592c-4459-9b98-fc5fbf0c6e90}_maxwidth=15 bottomlayer_{36f540e3-592c-4459-9b98-fc5fbf0c6e90}_prefwidth=15 maxuncoupledlength=1000
FabricationTestPointUsage TestPointUsage [All] p1: valid=2 allowmultiple=FALSE
FabricationTestpoint Testpoint [All] p1: side=3 testpointundercomponent=TRUE minsize=40 maxsize=100 preferedsize=60 minholesize=0 maxholesize=40 preferedholesize=32 testpointgrid=1 allowsidetop=TRUE allowsidebottom=TRUE usegrid=TRUE gridtolerance=0.01
FanoutControl Fanout_LCC [IsLCC] p1: bgadir=Out bgaviamode=Centered fanoutstyle=Auto fanoutdirection=Alternating viagrid=1 // Fanout_LCC (Default Rule)
FanoutControl Fanout_BGA [IsBGA] p2: bgadir=Out bgaviamode=Centered fanoutstyle=Auto fanoutdirection=Alternating viagrid=1 // Fanout_BGA (Default Rule)
FanoutControl Fanout_Default [All] p4: bgadir=Out bgaviamode=Centered fanoutstyle=Auto fanoutdirection=Alternating viagrid=1 // Fanout_Default (Default Rule)
FanoutControl Fanout_Small [(CompPinCount < 5)] p5: bgadir=Out bgaviamode=Centered fanoutstyle=Auto fanoutdirection=OutThenIn viagrid=1 // Fanout_Small (Default Rule)
Height [All] p1: minheight=0 maxheight=1968.5 prefheight=1968.5
HoleSize [All] p1: absolutevalues=TRUE maxlimit=251 minlimit=4 maxpercent=80.000 minpercent=20.000
HoleToHoleClearance [All] p1: gap=8 allowstackedmicrovias=TRUE
MinimumAnnularRing MinimumAnnularRing_ThermalPadVias [IsVia and InAnyComponent] p1: minimumring=5.91
MinimumAnnularRing [All] p2: minimumring=2
MinimumSolderMaskSliver MinimumSolderMaskSliver_Logo [InComponentClass('Logo') vs InComponentClass('Logo')] p1: minsoldermaskwidth=0.7
MinimumSolderMaskSliver [All] p2: minsoldermaskwidth=3.94
PlaneConnect [All] p1: planeconnectstyle=Relief reliefexpansion=10 reliefentries=4 reliefconductorwidth=10 reliefairgap=10
PolygonConnect [All] p1: connectstyle=Direct reliefconductorwidth=10 reliefentries=4 polygonreliefangle="90 Angle" airgapwidth=10
RoutingVias ThermalPadVias [IsVia and InAnyComponent] p1: holewidth=7.87 width=19.68 viastyle="Through Hole" minholewidth=7.87 minwidth=19.68 maxholewidth=12.99 maxwidth=23.62
RoutingVias [All] p2: holewidth=16 width=34 viastyle="Through Hole" minholewidth=4 minwidth=8 maxholewidth=100 maxwidth=150
SilkToBoardRegionClearance [Not ((IsComment or IsDesignator) And (Hide <> 'False')) and not InRegion(1000,500,4000,800)] p1:
SilkToSilkClearance SilkToSilkClearance_Pb-FreeLogo [(HasFootprint('Pb-Free_Overlay_Medium') OR HasFootprint('Pb-Free_Overlay_Small')) vs (HasFootprint('Pb-Free_Overlay_Medium') OR HasFootprint('Pb-Free_Overlay_Small'))] p1: silktosilkclearance=0
SilkToSilkClearance [All] p2: silktosilkclearance=3.94
SilkToSolderMaskClearance SilkToComponentPadClearance [(IsPad or IsFill or IsRegion) and InAnycomponent] p1: minsilkscreentomaskgap=5 clearancetoexposedcopper=TRUE
SilkToSolderMaskClearance "Silk to Solder Mask Opening" [All] p2: minsilkscreentomaskgap=3.94 clearancetoexposedcopper=FALSE
SolderMaskExpansion [All] p1: expansion=1.97 istentingtop=FALSE
UnRoutedNet [All] p1: checkbadconnections=TRUE
Width [All] p1: maxlimit=100 minlimit=6 preferedwidth=10 substack1={36F540E3-592C-4459-9B98-FC5FBF0C6E90} checkconnectedcopper=TRUE
12 further rules are at their usual default settings.

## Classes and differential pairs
net class HV: AC_L AC_L_CON AC_L_EMI AC_L_F AC_L_Sense_1 AC_L_Sense_2 AC_N AC_N_CON AC_N_EMI AC_N_Re DCLINK ISO_12V_H_RECT NetD3_1 NetD3_2 NetD4_1 NetD5_1 NetD6_1 NetD7_1 NetR127_2 NetR134_2 NetR142_1 NetR150_1 NetU42_13 PFC_4H_G VBATT VBATT_F
component class "PMP22650 CLLLC Power Stage": C1 C2 C3 C4 C5 C6 C7 C8 C9 C10 C11 C12 C13 C14 C15 C16 C17 C18 C19 C20 C21 C255 C256 C257 F1 F2 J1 J2 J3 J4 J5 J6 J7 J8 J9 J10 J11 J12 J13 J37 J38 L19 Q1 Q2 R1 R2 R3 R4 R5 T1 T2 T3 TP1 TP2 TP3
component class "PMP22650 CLLLC Primary Sensing": C126 C127 C128 C129 C130 C131 C132 C133 C134 C135 C136 C137 R66 R67 R68 R69 R70 R71 R72 R73 R74 R75 R76 R77 R78 R79 R80 R81 R82 R83 U24 U25 U26 U27
net class EARTH: EARTH
component class "PMP22650 PFC Power Stage": C202 C203 C204 C205 C206 C207 C208 C209 C210 C211 C212 C213 C214 C215 C216 C217 C218 C219 C220 C221 C222 C223 C224 C225 C226 C227 C228 C229 C230 C231 D4 D5 D6 D7 D8 D9 D10 F3 F4 J33 K1 L16 L17 L18 MP1 Q5 Q6 Q7 Q8 Q9 R125 R126 R127 R128 R129 R130 R131 R132 R133 R134 R135 R136 R137 R138 R139 R140 R141 R142 R143 R144 R145 R146 R147 R148 R149 R150 R151 R152 R153 R154 R155 R156 R157 R158 R159 R160 R161 R162 R163 R164 R165 R166 R167 R168 R169 R170 R171 R172 R173 R174 R175 TP5 TP6 TP7 TP8 U43 U44 U45 U46 U47
component class "PMP22650 PFC LF FET Gate Driver": C190 C191 C192 C193 C194 C195 C196 C197 C198 C199 C200 C201 D2 D3 J31 J32 R117 R118 R119 R120 R121 R122 R123 R124 U42
component class "PMP22650 PFC GaN PH2": C168 C169 C170 C171 C172 C173 C174 C175 C176 C177 C178 C179 C180 C181 C182 C183 C184 C185 C186 C187 C188 C189 J29 J30 L14 L15 R107 R108 R109 R110 R111 R112 R113 R114 R115 R116 U38 U39 U40 U41
component class "PMP22650 PFC GaN PH1": C146 C147 C148 C149 C150 C151 C152 C153 C154 C155 C156 C157 C158 C159 C160 C161 C162 C163 C164 C165 C166 C167 J27 J28 L12 L13 R97 R98 R99 R100 R101 R102 R103 R104 R105 R106 U34 U35 U36 U37
component class "PMP22650 Control": C138 C139 C140 C141 C142 C143 C144 C145 C251 C252 C253 C254 D1 J24 J25 J26 L11 R84 R85 R86 R87 R88 R89 R90 R91 R92 R93 R94 R95 R96 U28 U29 U30 U31 U32 U33 U51 U52
component class "PMP22650 CLLLC Secondary Sensing": C236 C237 C238 C239 C240 C241 C242 C243 C244 C245 C246 C247 C248 C249 C250 J35 J36 R178 R179 R180 R181 R182 R183 R184 R185 R186 R187 R188 R189 R190 R191 R192 R193 R194 R195 R196 R197 R198 R199 R200 R201 R202 R205 R206 R207 R208 U48 U49 U50
component class "PMP22650 CLLLC GaN Phase D": C104 C105 C106 C107 C108 C109 C110 C111 C112 C113 C114 C115 C116 C117 C118 C119 C120 C121 C122 C123 C124 C125 J22 J23 L9 L10 R56 R57 R58 R59 R60 R61 R62 R63 R64 R65 R215 R216 R217 R218 R219 R220 U20 U21 U22 U23
component class "PMP22650 CLLLC GaN Phase C": C82 C83 C84 C85 C86 C87 C88 C89 C90 C91 C92 C93 C94 C95 C96 C97 C98 C99 C100 C101 C102 C103 J20 J21 L7 L8 R46 R47 R48 R49 R50 R51 R52 R53 R54 R55 R209 R210 R211 R212 R213 R214 U16 U17 U18 U19
component class "PMP22650 CLLLC GaN Phase B": C60 C61 C62 C63 C64 C65 C66 C67 C68 C69 C70 C71 C72 C73 C74 C75 C76 C77 C78 C79 C80 C81 J18 J19 L5 L6 R36 R37 R38 R39 R40 R41 R42 R43 R44 R45 U12 U13 U14 U15
component class "PMP22650 CLLLC GaN Phase A": C38 C39 C40 C41 C42 C43 C44 C45 C46 C47 C48 C49 C50 C51 C52 C53 C54 C55 C56 C57 C58 C59 J16 J17 L3 L4 R26 R27 R28 R29 R30 R31 R32 R33 R34 R35 U8 U9 U10 U11
component class "PMP22650 Bias Power and Monitors": C22 C23 C24 C25 C26 C27 C28 C29 C30 C31 C32 C33 C34 C35 C36 C37 J15 L2 Q3 Q4 R6 R7 R8 R9 R10 R11 R12 R13 R14 R15 R16 R17 R18 R19 R20 R21 R22 R23 R24 R25 R203 R204 U1 U2 U3 U4 U5 U6 U7
component class "PMP22650 Active EMI": C232 C233 C234 C235 J34 Q10 R176 R177
component class Header: U28
net class HV_SW: 5V_H_A 5V_H_B 5V_H_C 5V_H_D 5V_H_PFC_1 5V_H_PFC_2 FAULT_H_A FAULT_H_B FAULT_H_C FAULT_H_D FAULT_H_PFC_1 FAULT_H_PFC_2 IN_H_A IN_H_B IN_H_C IN_H_D IN_H_PFC_1 IN_H_PFC_2 ISO_12V_H_A ISO_12V_H_B ISO_12V_H_C ISO_12V_H_D ISO_12V_H_PFC_1 ISO_12V_H_PFC_2 LC_GATE LC_GND LC_SW_NODE NetL4_2 NetL6_2 NetL8_2 NetL10_2 NetL13_2 NetL15_2 NetR34_1 NetR44_1 NetR54_1 NetR64_1 NetR105_1 NetR115_1 NetR212_1 NetR213_1 NetR214_1 NetR218_1 NetR219_1 NetR220_1 OC_H_A OC_H_B OC_H_C OC_H_D OC_H_PFC_1 OC_H_PFC_2 RDRV_H_A RDRV_H_B RDRV_H_C RDRV_H_D RDRV_H_PFC_1 RDRV_H_PFC_2 SW_A SW_A_RES SW_A_XFMR SW_B SW_B_RES SW_C SW_C_RES SW_C_XFMR SW_D SW_D_RES TEMP_H_A TEMP_H_B TEMP_H_C TEMP_H_D TEMP_H_PFC_1 TEMP_H_PFC_2 TTPLPFC_SW1 TTPLPFC_SW2 VNEG_H_A VNEG_H_B VNEG_H_C VNEG_H_D VNEG_H_PFC_1 VNEG_H_PFC_2
component class Logo: Logo1
component class "PMP22650 Hardware": LBL1 Logo1 Logo2 Logo3 Logo4 LOGO5 LOGO6 LOGO8 LOGO9 ZZ1 ZZ2 ZZ3 ZZ4
component class AssemblyNote: ZZ1 ZZ2 ZZ3 ZZ4
component class Label: LBL1

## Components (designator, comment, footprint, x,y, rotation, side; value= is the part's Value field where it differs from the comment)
C1 "AY2222M35Y5US63L7" AY2_950x500_Straight 8294,321 r180 top value=2200pF
C2 "C1210X333JBGACAUTO" FP-C1210X333JBGACAUTO_1210-MFG 6619.27,913.6 r270 bottom value=33nF
C3 "C1210X333JBGACAUTO" FP-C1210X333JBGACAUTO_1210-MFG 10136.5,1816.96 r90 bottom value=33nF
C4 "C1210X333JBGACAUTO" FP-C1210X333JBGACAUTO_1210-MFG 6771.27,913.6 r270 bottom value=33nF
C5 "C1210X333JBGACAUTO" FP-C1210X333JBGACAUTO_1210-MFG 10001.27,1816.96 r90 bottom value=33nF
C6 "C1210X333JBGACAUTO" FP-C1210X333JBGACAUTO_1210-MFG 6913.27,913.6 r270 bottom value=33nF
C7 "C1210X333JBGACAUTO" FP-C1210X333JBGACAUTO_1210-MFG 10004,1813.31 r90 top value=33nF
C8 "C1210X333JBGACAUTO" FP-C1210X333JBGACAUTO_1210-MFG 7055.27,914.6 r270 bottom value=33nF
C9 "C1210X333JBGACAUTO" FP-C1210X333JBGACAUTO_1210-MFG 10139.23,1813.31 r90 top value=33nF
C10 "C1210X333JBGACAUTO" FP-C1210X333JBGACAUTO_1210-MFG 6962.66,3369.62 r90 top value=33nF
C11 "C1210X333JBGACAUTO" FP-C1210X333JBGACAUTO_1210-MFG 10104,2593 r90 bottom value=33nF
C12 "C1210X333JBGACAUTO" FP-C1210X333JBGACAUTO_1210-MFG 7102.66,3369.62 r90 top value=33nF
C13 "C1210X333JBGACAUTO" FP-C1210X333JBGACAUTO_1210-MFG 10237,2593 r90 bottom value=33nF
C14 "C1210X333JBGACAUTO" FP-C1210X333JBGACAUTO_1210-MFG 7102.64,3369.62 r90 bottom value=33nF
C15 "C1210X333JBGACAUTO" FP-C1210X333JBGACAUTO_1210-MFG 10235.6,2590.8 r90 top value=33nF
C16 "C1210X333JBGACAUTO" FP-C1210X333JBGACAUTO_1210-MFG 6967.64,3369.62 r90 bottom value=33nF
C17 "C1210X333JBGACAUTO" FP-C1210X333JBGACAUTO_1210-MFG 10093.81,2589.52 r90 top value=33nF
C18 "ALA8DA301CF500" FP-ALA8DA301CF500_RADIAL-MFG 10004.86,612.54 r180 top value=300µF
C19 "B58031I5105M002" B58031I_1084x785x450 10036.27,4089.6 r0 bottom value=1uF
C20 "ALA8DA301CF500" FP-ALA8DA301CF500_RADIAL-MFG 10041.42,3838.57 r180 top value=300µF
C21 "B58031I5105M002" B58031I_1084x785x450 10004.27,350.6 r0 bottom value=1uF
C22 "CGA2B3X7R1E104K050BB" 0402 5345.22,3827.65 r0 bottom value=0.1uF
C23 "GCM155R71E223KA55D" 0402 5428.58,3094.66 r90 top value=0.022uF
C24 "CGA2B3X7R1E104K050BB" 0402 5944.27,4382.55 r180 top value=0.1uF
C25 "CGA2B3X7R1E104K050BB" 0402 5730.34,4334.28 r270 top value=0.1uF
C26 "CGA2B3X7R1E104K050BB" 0402 5313.27,3297.6 r90 top value=0.1uF
C27 "GCM155R71C104JA55D" 0402 6093.24,2340.57 r270 top value=0.1uF
C28 "GCM155R71C104JA55D" 0402 6070.85,2449.46 r180 top value=0.1uF
C29 "GCM155R71C104JA55D" 0402 6196,2503 r0 top value=0.1uF
C30 "GCM155R71C104JA55D" 0402 6117,2012 r0 top value=0.1uF
C31 "C1206C106J3RACAUTO" 1206_180 5248.27,4357.6 r90 top value=10uF
C32 "GRT31CC81A226KE01L" 1206_180 5408.27,4192.6 r180 top value=22uF
C33 "CGA2B3X7R1E104K050BB" 0402 5935.82,4168.9 r180 top value=0.1uF
C34 "CGA2B3X7R1E104K050BB" 0402 5935.82,4210.9 r180 top value=0.1uF
C35 "CGA2B3X7R1E104K050BB" 0402 6053.05,4283.9 r270 top value=0.1uF
C36 "CGA3E1X7R1E105K080AD" 0603 6112.05,4282.9 r90 top value=1uF
C37 "GCM155R71C104JA55D" 0402 6115.82,2173.29 r0 top value=0.1uF
C38 "CGA4J3X7R1E225K125AB" 0805_HV 6332.27,3963.6 r180 top value=2.2uF
C39 "GRT155R6YA105KE13D" 0402 6500,3481 r180 top value=1uF
C40 "GCM155R71H104KE02D" 0402 6507.27,3843.6 r180 top value=0.1uF
C41 "GCM1555C1H680JA16D" FP-GCM1555C1H680JA16D_0402-MFG#1 6345.84,3479.75 r0 top value=68pF
C42 "GCM1555C1H220JA16D" 0402 6430.27,4018.6 r180 top value=22pF
C43 "GCM155R71C224KE02D" 0402 6554,3941 r0 top value=0.22uF
C44 "TMK316AB7106KLHT" 1206_180 6345,4099 r180 top value=10uF
C45 "C1206C223KDRACTU" 1206_190 6093.02,3729.6 r0 bottom value=0.022uF
C46 "C1206C223KDRACTU" 1206_190 6093.02,3636.6 r0 bottom value=0.022uF
C47 "C1812X104KDRACAUTO" FP-C1812X104KDRACAUTO_1812-MFG#1 6080.27,3482.6 r180 bottom value=100nF
C48 "C1812X104KDRACAUTO" FP-C1812X104KDRACAUTO_1812-MFG#1 6079.27,4045.6 r180 bottom value=100nF
C49 "C1206C223KDRACTU" 1206_190 6093.02,3819.63 r0 bottom value=0.022uF
C50 "C1206C223KDRACTU" 1206_190 6093.02,3909.6 r0 bottom value=0.022uF
C51 "C1812X104KDRACAUTO" FP-C1812X104KDRACAUTO_1812-MFG#1 5850,3867 r270 bottom value=100nF
C52 "C1812X104KDRACAUTO" FP-C1812X104KDRACAUTO_1812-MFG#1 6082,3324 r180 bottom value=100nF
C53 "CGA4J3X7R1E225K125AB" 0805_HV 6880,3870 r180 top value=2.2uF
C54 "GRT155R6YA105KE13D" 0402 7077.27,4378.6 r0 top value=1uF
C55 "GCM155R71H104KE02D" 0402 7105,4035 r0 top value=0.1uF
C56 "GCM1555C1H680JA16D" FP-GCM1555C1H680JA16D_0402-MFG#1 7242.27,4373.6 r180 top value=68pF
C57 "GCM1555C1H220JA16D" 0402 6921,4004 r180 top value=22pF
C58 "GCM155R71C224KE02D" 0402 7094,3996 r0 top value=0.22uF
C59 "TMK316AB7106KLHT" 1206_180 6843,4131 r180 top value=10uF
C60 "CGA4J3X7R1E225K125AB" 0805_HV 7418,261 r90 top value=2.2uF
C61 "GRT155R6YA105KE13D" 0402 5918.27,436.95 r90 bottom value=1uF
C62 "GCM155R71H104KE02D" 0402 6220.64,426.05 r90 top value=0.1uF
C63 "GCM1555C1H680JA16D" FP-GCM1555C1H680JA16D_0402-MFG#1 5928.27,576.05 r270 bottom value=68pF
C64 "GCM1555C1H220JA16D" 0402 7340,230 r0 top value=22pF
C65 "GCM155R71C224KE02D" 0402 7198,177 r180 top value=0.22uF
C66 "TMK316AB7106KLHT" 1206_180 7431,153 r0 top value=10uF
C67 "C1206C223KDRACTU" 1206_190 6356.07,638.98 r180 bottom value=0.022uF
C68 "C1206C223KDRACTU" 1206_190 6356.07,548.98 r180 bottom value=0.022uF
C69 "C1812X104KDRACAUTO" FP-C1812X104KDRACAUTO_1812-MFG#1 6339,802 r0 bottom value=100nF
C70 "C1812X104KDRACAUTO" FP-C1812X104KDRACAUTO_1812-MFG#1 6119,361 r270 bottom value=100nF
C71 "C1206C223KDRACTU" 1206_190 6356.07,458.98 r180 bottom value=0.022uF
C72 "C1206C223KDRACTU" 1206_190 6356.07,368.98 r180 bottom value=0.022uF
C73 "C1812X104KDRACAUTO" FP-C1812X104KDRACAUTO_1812-MFG#1 6342,164 r0 bottom value=100nF
C74 "C1812X104KDRACAUTO" FP-C1812X104KDRACAUTO_1812-MFG#1 6119,601 r90 bottom value=100nF
C75 "CGA4J3X7R1E225K125AB" 0805_HV 6900,258 r90 top value=2.2uF
C76 "GRT155R6YA105KE13D" 0402 5926,146 r90 bottom value=1uF
C77 "GCM155R71H104KE02D" 0402 6220.38,124 r90 top value=0.1uF
C78 "GCM1555C1H680JA16D" FP-GCM1555C1H680JA16D_0402-MFG#1 5928.27,288.42 r270 bottom value=68pF
C79 "GCM1555C1H220JA16D" 0402 6827,257 r90 top value=22pF
C80 "GCM155R71C224KE02D" 0402 6674,167 r180 top value=0.22uF
C81 "TMK316AB7106KLHT" 1206_180 6905,150 r0 top value=10uF
C82 "CGA4J3X7R1E225K125AB" 0805_HV 9681,3168 r90 top value=2.2uF
C83 "GRT155R6YA105KE13D" 0402 8099,3764 r90 top value=1uF
C84 "GCM155R71H104KE02D" 0402 8485,3748 r0 top value=0.1uF
C85 "GCM1555C1H680JA16D" FP-GCM1555C1H680JA16D_0402-MFG#1 8104,3927 r270 top value=68pF
C86 "GCM1555C1H220JA16D" 0402 9828,3221 r180 top value=22pF
C87 "GCM155R71C224KE02D" 0402 10013.27,3203.6 r0 top value=0.22uF
C88 "TMK316AB7106KLHT" 1206_180 9827,3156 r0 top value=10uF
C89 "C1206C223KDRACTU" 1206_190 9518.27,3165.61 r0 bottom value=0.022uF
C90 "C1206C223KDRACTU" 1206_190 9518.27,3075.5 r0 bottom value=0.022uF
C91 "C1812X104KDRACAUTO" FP-C1812X104KDRACAUTO_1812-MFG#1 9505.76,3126.24 r180 top value=100nF
C92 "C1812X104KDRACAUTO" FP-C1812X104KDRACAUTO_1812-MFG#1 9508,3645 r180 bottom value=100nF
C93 "C1206C223KDRACTU" 1206_190 9518.27,3255.5 r0 bottom value=0.022uF
C94 "C1206C223KDRACTU" 1206_190 9518.27,3346.5 r0 bottom value=0.022uF
C95 "C1812X104KDRACAUTO" FP-C1812X104KDRACAUTO_1812-MFG#1 9505.76,3294.87 r180 top value=100nF
C96 "C1812X104KDRACAUTO" FP-C1812X104KDRACAUTO_1812-MFG#1 9508.27,3483.6 r180 bottom value=100nF
C97 "CGA4J3X7R1E225K125AB" 0805_HV 10173,3171 r90 top value=2.2uF
C98 "GRT155R6YA105KE13D" 0402 8106,4183 r90 top value=1uF
C99 "GCM155R71H104KE02D" 0402 8440,4178 r90 top value=0.1uF
C100 "GCM1555C1H680JA16D" FP-GCM1555C1H680JA16D_0402-MFG#1 8104,4352 r270 top value=68pF
C101 "GCM1555C1H220JA16D" 0402 10352,3275 r180 top value=22pF
C102 "GCM155R71C224KE02D" 0402 10509,3275 r0 top value=0.22uF
C103 "TMK316AB7106KLHT" 1206_180 10361,3173 r0 top value=10uF
C104 "CGA4J3X7R1E225K125AB" 0805_HV 10640.11,1214.56 r90 top value=2.2uF
C105 "GRT155R6YA105KE13D" 0402 8111,68 r90 top value=1uF
C106 "GCM155R71H104KE02D" 0402 8468,184 r90 top value=0.1uF
C107 "GCM1555C1H680JA16D" FP-GCM1555C1H680JA16D_0402-MFG#1 8116,187 r270 top value=68pF
C108 "GCM1555C1H220JA16D" 0402 10503,1077 r90 top value=22pF
C109 "GCM155R71C224KE02D" 0402 10339.27,1205.6 r270 top value=0.22uF
C110 "TMK316AB7106KLHT" 1206_180 10493,1258 r180 top value=10uF
C111 "C1206C223KDRACTU" 1206_190 9517.96,1290.15 r180 bottom value=0.022uF
C112 "C1206C223KDRACTU" 1206_190 9517.96,1380.15 r180 bottom value=0.022uF
C113 "C1812X104KDRACAUTO" FP-C1812X104KDRACAUTO_1812-MFG#1 9531.02,1254.75 r0 top value=100nF
C114 "C1812X104KDRACAUTO" FP-C1812X104KDRACAUTO_1812-MFG#1 9529.06,1587.62 r0 top value=100nF
C115 "C1206C223KDRACTU" 1206_190 9517.96,1470.15 r180 bottom value=0.022uF
C116 "C1206C223KDRACTU" 1206_190 9517.96,1560.03 r180 bottom value=0.022uF
C117 "C1812X104KDRACAUTO" FP-C1812X104KDRACAUTO_1812-MFG#1 9498.27,1063.6 r0 bottom value=100nF
C118 "C1812X104KDRACAUTO" FP-C1812X104KDRACAUTO_1812-MFG#1 9531.02,1419.55 r0 top value=100nF
C119 "CGA4J3X7R1E225K125AB" 0805_HV 10157,1279 r90 top value=2.2uF
C120 "GRT155R6YA105KE13D" 0402 8118,482 r90 top value=1uF
C121 "GCM155R71H104KE02D" 0402 8454,637 r90 top value=0.1uF
C122 "GCM1555C1H680JA16D" FP-GCM1555C1H680JA16D_0402-MFG#1 8116,628 r270 top value=68pF
C123 "GCM1555C1H220JA16D" 0402 10008,1348 r180 top value=22pF
C124 "GCM155R71C224KE02D" 0402 9797.27,1229.22 r270 top value=0.22uF
C125 "TMK316AB7106KLHT" 1206_180 9990,1281 r0 top value=10uF
C126 "CGA2B3X7R1E104K050BB" 0402 5974.24,3330.5 r90 top value=0.1uF
C127 "04025U100CAT2A" 0402 5546.57,3339.46 r180 top value=10pF
C128 "CGA2B2X7R1H222K050BA" 0402 6296.27,3358.6 r270 top value=2200pF
C129 "CGA2B3X7R1E104K050BB" 0402 6114.27,3455.6 r180 top value=0.1uF
C130 "04025U100CAT2A" 0402 6113.27,3253.6 r0 top value=10pF
C131 "GCM155R71H471KA37D" 0402 5076.92,3825.6 r270 bottom value=470pF
C132 "GCM155R71C104JA55D" 0402 5943,3630 r0 top value=0.1uF
C133 "CGA2B3X7R1E104K050BB" 0402 5165.71,3705.16 r180 bottom value=0.1uF
C134 "GCM155R71C104JA55D" 0402 5938.27,3392.6 r0 top value=0.1uF
C135 "04025U100CAT2A" 0402 6384.74,2047.32 r90 top value=10pF
C136 "CGA2B3X7R1E104K050BB" 0402 6321.36,2225.32 r0 top value=0.1uF
C137 "CGA2B3X7R1E104K050BB" 0402 5195.88,2882.08 r0 bottom value=0.1uF
C138 "CGA3E2X7R2A472K080AA" 0603 3899.7,4733.6 r270 bottom value=4700pF
C139 "CGA2B3X7R1E104K050BB" 0402 2753.27,4717.6 r90 bottom value=0.1uF
C140 "CGA2B3X7R1E104K050BB" 0402 3338.27,4727.6 r90 bottom value=0.1uF
C141 "GCM1885C1H471JA16D" 0603 5493.27,3477.6 r270 top value=470pF
C142 "CGA2B3X7R1E104K050BB" 0402 4959,2530 r270 bottom value=0.1uF
C143 "CGA2B3X7R1E104K050BB" 0402 4971.92,2310.1 r270 bottom value=0.1uF
C144 "CGA2B3X7R1E104K050BB" 0402 5198,1399 r0 bottom value=0.1uF
C145 "CGA2B3X7R1E104K050BB" 0402 5195.41,1576.09 r0 bottom value=0.1uF
C146 "CGA4J3X7R1E225K125AB" 0805_HV 4358.27,2207.6 r90 top value=2.2uF
C147 "GRT155R6YA105KE13D" 0402 5030.57,2093.29 r90 top value=1uF
C148 "GCM155R71H104KE02D" 0402 4735.27,2081.13 r90 bottom value=0.1uF
C149 "GCM1555C1H680JA16D" FP-GCM1555C1H680JA16D_0402-MFG#1 5030.57,1985.13 r90 top value=68pF
C150 "GCM1555C1H220JA16D" 0402 4466.27,2185.6 r90 top value=22pF
C151 "GCM155R71C224KE02D" 0402 4571.27,2063.26 r270 bottom value=0.22uF
C152 "TMK316AB7106KLHT" 1206_180 4598.27,2282.6 r90 bottom value=10uF
C153 "C1206C223KDRACTU" 1206_190 4442.08,3596.23 r270 bottom value=0.022uF
C154 "C1206C223KDRACTU" 1206_190 4262.08,3596.23 r270 bottom value=0.022uF
C155 "C1812X104KDRACAUTO" FP-C1812X104KDRACAUTO_1812-MFG#2 4667.27,3613.6 r90 bottom value=100nF
C156 "C1812X104KDRACAUTO" FP-C1812X104KDRACAUTO_1812-MFG#2 4120.27,3859.6 r0 bottom value=100nF
C157 "C1206C223KDRACTU" 1206_190 4352.08,3596.23 r270 bottom value=0.022uF
C158 "C1206C223KDRACTU" 1206_190 4172.08,3596.23 r270 bottom value=0.022uF
C159 "C1812X104KDRACAUTO" FP-C1812X104KDRACAUTO_1812-MFG#2 4034.97,3597.46 r90 bottom value=100nF
C160 "C1812X104KDRACAUTO" FP-C1812X104KDRACAUTO_1812-MFG#2 4734.89,3827.65 r180 bottom value=100nF
C161 "CGA4J3X7R1E225K125AB" 0805_HV 4328.27,1787.6 r90 top value=2.2uF
C162 "GRT155R6YA105KE13D" 0402 5069,1833 r270 top value=1uF
C163 "GCM155R71H104KE02D" 0402 4717,1684 r180 top value=0.1uF
C164 "GCM1555C1H680JA16D" FP-GCM1555C1H680JA16D_0402-MFG#2 5064,1681 r90 top value=68pF
C165 "GCM1555C1H220JA16D" 0402 4527.09,1687.23 r90 top value=22pF
C166 "GCM155R71C224KE02D" 0402 4567,1545 r270 bottom value=0.22uF
C167 "TMK316AB7106KLHT" 1206_180 4595.27,1740.1 r90 bottom value=10uF
C168 "CGA4J3X7R1E225K125AB" 0805_HV 4598.27,3414.2 r180 bottom value=2.2uF
C169 "GRT155R6YA105KE13D" 0402 5093.27,3092.6 r90 top value=1uF
C170 "GCM155R71H104KE02D" 0402 4816.47,3256.1 r90 bottom value=0.1uF
C171 "GCM1555C1H680JA16D" FP-GCM1555C1H680JA16D_0402-MFG#1 5148.29,3232.48 r270 bottom value=68pF
C172 "GCM1555C1H220JA16D" 0402 4297.27,3047.6 r90 top value=22pF
C173 "GCM155R71C224KE02D" 0402 4574.65,3118.88 r270 bottom value=0.22uF
C174 "TMK316AB7106KLHT" 1206_180 4594,3268 r90 bottom value=10uF
C175 "C1206C223KDRACTU" 1206_190 4442.32,1165.76 r270 bottom value=0.022uF
C176 "C1206C223KDRACTU" 1206_190 4352.32,1165.76 r270 bottom value=0.022uF
C177 "C1812X104KDRACAUTO" FP-C1812X104KDRACAUTO_1812-MFG#2 4589.27,921.6 r180 bottom value=100nF
C178 "C1812X104KDRACAUTO" FP-C1812X104KDRACAUTO_1812-MFG#2 4029.27,1167.6 r90 bottom value=100nF
C179 "C1206C223KDRACTU" 1206_190 4262.32,1165.76 r270 bottom value=0.022uF
C180 "C1206C223KDRACTU" 1206_190 4172.32,1165.76 r270 bottom value=0.022uF
C181 "C1812X104KDRACAUTO" FP-C1812X104KDRACAUTO_1812-MFG#2 4576.3,1163.63 r90 bottom value=100nF
C182 "C1812X104KDRACAUTO" FP-C1812X104KDRACAUTO_1812-MFG#2 4127.27,937.6 r0 bottom value=100nF
C183 "CGA4J3X7R1E225K125AB" 0805_HV 4333,2770 r90 top value=2.2uF
C184 "GRT155R6YA105KE13D" 0402 5054,2921 r270 top value=1uF
C185 "GCM155R71H104KE02D" 0402 4722,2896 r270 top value=0.1uF
C186 "GCM1555C1H680JA16D" FP-GCM1555C1H680JA16D_0402-MFG#2 5048,2766 r90 top value=68pF
C187 "GCM1555C1H220JA16D" 0402 4394,2757 r90 top value=22pF
C188 "GCM155R71C224KE02D" 0402 4449,2618 r270 top value=0.22uF
C189 "TMK316AB7106KLHT" 1206_180 4609.27,2808.6 r90 bottom value=10uF
C190 "CGA4J1X7R1E475K125AC" 0805L 2850.27,4390.6 r270 bottom value=4.7uF
C191 "CGA3E2X7R1E104K080AA" 0603 2846,4383 r270 top value=0.1uF
C192 "C0603C103J3GECAUTO" 0603 2910,4382 r270 top value=0.01uF
C193 "CGA3E2NP01H101J080AA" 0603 3090.27,4157.6 r90 bottom value=100pF
C194 "CGA3E2NP01H101J080AA" 0603 3195.65,4204.6 r90 bottom value=100pF
C195 "CGA2B2X7R1H222K050BA" 0402 3141.01,4267.62 r270 bottom value=2200pF
C196 "CGA2B2X7R1H102K050BA" 0402 2932.27,1385.6 r0 top value=1000pF
C197 "CGA2B2X7R1H102K050BA" 0402 2931.27,3644.6 r180 bottom value=1000pF
C198 "CGA3E2X7R1E104K080AA" 0603 3089.27,4279.6 r270 bottom value=0.1uF
C199 "CGA4J1X7R1E475K125AC" 0805L 2853.27,4105.6 r270 bottom value=4.7uF
C200 "CGA3E2X7R1E104K080AA" 0603 2902,4103 r270 top value=0.1uF
C201 "C0603C103J3GECAUTO" 0603 2846,4103 r270 top value=0.01uF
C202 "GCM155R71C104JA55D" 0402 5523.27,3297.6 r180 top value=0.1uF
C203 "GCM155R71C104JA55D" 0402 5943,3669 r0 top value=0.1uF
C204 "CGA2B2C0G1H101J050BA" 0402 2049.27,2280.6 r270 bottom value=100pF
C205 "CGA2B3X7R1E104K050BB" 0402 5136.62,653.6 r270 bottom value=0.1uF
C206 "CGA2B3X7R1E104K050BB" 0402 4023.14,4199.95 r0 bottom value=0.1uF
C207 "GCM1885C1H471JA16D" 0603 5495.27,3627.6 r270 top value=470pF
C208 "C0402C104K4RACAUTO" 0402 2134,2337 r0 top value=0.1uF
C209 "GCM155R71C104JA55D" 0402 5593.58,3708.61 r90 bottom value=0.1uF
C210 "GCM1885C1H471JA16D" 0603 5940,3716 r0 top value=470pF
C211 "CGA2B2C0G1H101J050BA" 0402 2061.27,2627.6 r90 top value=100pF
C212 "CGA2B3X7R1E104K050BB" 0402 3721.89,4197.57 r0 bottom value=0.1uF
C213 "C0603C102J5RACAUTO" 0603 3644.27,862.6 r270 top value=1000pF
C214 "CGA4J1X7S1C106K125AC" 0805_HV 3644.27,1054.6 r270 top value=10uF
C215 "C0402C104K4RACAUTO" 0402 2036.24,2480.9 r0 bottom value=0.1uF
C216 "AY2472M49Y5US63L7" AY2_1300x500_Straight 1582,1654 r0 top value=4700pF
C217 "AY2472M49Y5US63L7" AY2_1300x500_Straight 2159.18,255.91 r270 top value=4700pF
C218 "B32923H3225M000" FP-B32923H3225M000_RADIAL-MFG 521.35,3194.6 r0 top value=2.2µF
C219 "B32923H3225M000" FP-B32923H3225M000_RADIAL-MFG 769,1490 r0 top value=2.2µF
C220 "B32923H3225M000" FP-B32923H3225M000_RADIAL-MFG 2815.17,285.63 r180 top value=2.2µF
C221 "AY2472M49Y5US63L7" AY2_1300x500_Straight 116,1501 r90 top value=4700pF
C222 "AY2472M49Y5US63L7" AY2_1300x500_Straight 3468.27,256.63 r270 top value=4700pF
C223 "ALA7DA471DE500" FP-ALA7DA471DE500_RADIAL-MFG 4715.42,3731.6 r180 top value=470µF
C224 "ALA7DA471DE500" FP-ALA7DA471DE500_RADIAL-MFG 4619.19,954.91 r180 top value=470µF
C225 "ALA7DA471DE500" FP-ALA7DA471DE500_RADIAL-MFG 1850.27,3739.75 r90 top value=470µF
C226 "C1812X104KDRACAUTO" FP-C1812X104KDRACAUTO_1812-MFG#1 3282.55,1416.42 r0 top value=100nF
C227 "C1812X104KDRACAUTO" FP-C1812X104KDRACAUTO_1812-MFG#1 3321.15,3246.41 r180 top value=100nF
C228 "C1812X104KDRACAUTO" FP-C1812X104KDRACAUTO_1812-MFG#1 3321.15,3403.84 r180 top value=100nF
C229 "C1812X104KDRACAUTO" FP-C1812X104KDRACAUTO_1812-MFG#1 3282.55,1572.89 r0 top value=100nF
C230 "C1812X104KDRACAUTO" FP-C1812X104KDRACAUTO_1812-MFG#2 3321.15,3571.41 r180 top value=100nF
C231 "C1812X104KDRACAUTO" FP-C1812X104KDRACAUTO_1812-MFG#2 3282.55,1736.42 r0 top value=100nF
C232 "CGA2B2C0G1H100D050BA" 0402 5386.3,2344.41 r270 top value=10pF
C233 "CGA2B2C0G1H151J050BA" 0402 5331.41,2564.84 r0 top value=150pF
C234 "AY2101K29Y5SS63L7" FP-AY2101K29Y5SS63L7_RADIAL-MFG 3969.27,258.6 r90 top value=100pF
C235 "AY2472M49Y5US63L7" AY2_1300x500_Straight 3741.27,258.6 r270 top value=4700pF
C236 "CGA2B3X7R1E104K050BB" 0402 6283,3017 r0 bottom value=0.1uF
C237 "04025U100CAT2A" 0402 5943,3495 r0 top value=10pF
C238 "CGA2B2X7R1H222K050BA" 0402 6223,3017 r180 bottom value=2200pF
C239 "CGA2B3X7R1E104K050BB" 0402 6297,3127 r270 top value=0.1uF
C240 "04025U100CAT2A" 0402 6215,3142 r90 bottom value=10pF
C241 "CGA2B3X7R1H223K050BB" 0402 5543.27,3402.6 r270 top value=0.022uF
C242 "CGA2B3X7R1H103K050BB" 0402 5524.92,3355.6 r270 bottom value=0.01uF
C243 "CGA2B3X7R1H103K050BB" 0402 5463.3,3207.02 r270 bottom value=0.01uF
C244 "CGA2B3X7R1E104K050BB" 0402 5454.17,3390.6 r0 top value=0.1uF
C245 "CGA2B3X7R1H103K050BB" 0402 5391.02,3290.73 r180 bottom value=0.01uF
C246 "CGA2B3X7R1H223K050BB" 0402 5545.27,3602.6 r90 top value=0.022uF
C247 "CGA2B3X7R1H103K050BB" 0402 5258.87,3445.41 r0 bottom value=0.01uF
C248 "CGA2B3X7R1H103K050BB" 0402 5351.76,3574.17 r90 bottom value=0.01uF
C249 "CGA2B3X7R1E104K050BB" 0402 5487.5,3552.31 r0 top value=0.1uF
C250 "CGA2B3X7R1H103K050BB" 0402 5497.49,3651.65 r180 bottom value=0.01uF
C251 "CGA2B3X7R1E104K050BB" 0402 2668.27,4757.6 r270 bottom value=0.1uF
C252 "CGA2B3X7R1E104K050BB" 0402 2333.27,4972.6 r270 bottom value=0.1uF
C253 "CGA2B3X7R1E104K050BB" 0402 2683.27,4972.6 r90 bottom value=0.1uF
C254 "CGA2B3X7R1E104K050BB" 0402 2328.27,4592.6 r90 bottom value=0.1uF
C255 "AY2222M35Y5US63L7" AY2_950x500_Straight 8300.27,4057.6 r180 top value=2200pF
C256 "C1206C223KDRACTU" 1206_190 7138,1317 r90 top value=0.022uF
C257 "C1206C223KDRACTU" 1206_190 6644,1369 r270 top value=0.022uF
D1 "NUP2105LT1G" SOT-23 3898.27,4867.6 r270 bottom value=24V
D2 "NRVBA340T3G" FP-NRVBA340T3G_SMA-MFG 2486.27,1465.6 r270 top
D3 "NRVBA340T3G" FP-NRVBA340T3G_SMA-MFG 3015.27,3972.6 r0 bottom
D4 "US1MDFQ-13" FP-US1MDFQ-13_D-FLAT-MFG 4359.19,594.8 r180 bottom
D5 "US1MDFQ-13" FP-US1MDFQ-13_D-FLAT-MFG 4357.16,728.8 r180 bottom
D6 "US1MDFQ-13" FP-US1MDFQ-13_D-FLAT-MFG 4382.62,258.6 r180 bottom
D7 "US1MDFQ-13" FP-US1MDFQ-13_D-FLAT-MFG 4381.62,402.6 r180 bottom
D8 "BAT165E6327HTSA1" SOD-323 3476.14,989.64 r270 top value=40V
D9 "BZT52B5V1-G3-18" SOD-123 3476.14,831.1 r90 top value=5.1V
D10 "TS40P05GHD2G" FP-TS40P05GHD2G_SIP4-MFG 4737,104 r0 top
F1 "0525025.MXEP_vm" FP-0525025.MXEP_vm_AXIAL-MFG 10511.6,2067 r180 top
F2 "0525025.MXEP_vm" FP-0525025.MXEP_vm_AXIAL-MFG 10292,2282 r0 top
F3 "0525025.MXEP_vm" FP-0525025.MXEP_vm_AXIAL-MFG 456.8,4084.2 r90 top
F4 "0525025.MXEP_vm" FP-0525025.MXEP_vm_AXIAL-MFG 241.53,4301.72 r270 top
J1 "292161-2" FP-292161-2_HDR2-MFG 6190.41,2938.12 r0 top
J2 "S1621-46R" Harwin_S1621-46R 5690.09,2306.54 r0 bottom
J3 "S1621-46R" Harwin_S1621-46R 5690.09,2171.51 r0 bottom
J4 "S1621-46R" Harwin_S1621-46R 5690.09,2441.42 r0 bottom
J5 "S1621-46R" Harwin_S1621-46R 5690.09,2576.45 r0 bottom
J6 "S1621-46R" Harwin_S1621-46R 5690.09,1822.82 r0 bottom
J7 "282856-3" TE_282856-3 10872.58,3949.44 r90 top
J8 "S1621-46R" Harwin_S1621-46R 5690.09,1957.85 r0 bottom
J9 "S1621-46R" Harwin_S1621-46R 5690.55,2772.5 r0 bottom
J10 "282856-3" TE_282856-3 10889,2002.75 r90 top
J11 "S1621-46R" Harwin_S1621-46R 5690.55,2907.53 r0 bottom
J12 "SSW-103-22-F-D-VS-K" SAMTEC_SSW-103-22-F-D-VS-K 6220,1337 r180 top
J13 "SSW-102-22-F-D-VS" FP-SSW-102-22-F-D-VS_RCPT4-MFG 6959.82,1337 r180 top
J15 "282856-2" TE_282856-2 5599,4696 r180 top
J16 "SSW-103-22-F-D-VS-K" SAMTEC_SSW-103-22-F-D-VS-K 7425.01,3805.57 r0 top
J17 "SSW-102-22-F-D-VS" FP-SSW-102-22-F-D-VS_RCPT4-MFG 6675.01,3821.7 r0 top
J18 "SSW-103-22-F-D-VS-K" SAMTEC_SSW-103-22-F-D-VS-K 6422,819 r180 top
J19 "SSW-102-22-F-D-VS" FP-SSW-102-22-F-D-VS_RCPT4-MFG 7172,817.87 r180 top
J20 "SSW-103-22-F-D-VS-K" SAMTEC_SSW-103-22-F-D-VS-K 7893,3864.97 r180 top
J21 "SSW-102-22-F-D-VS" FP-SSW-102-22-F-D-VS_RCPT4-MFG 8643,3865 r180 top
J22 "SSW-103-22-F-D-VS-K" SAMTEC_SSW-103-22-F-D-VS-K 7902,498.13 r180 top
J23 "SSW-102-22-F-D-VS" FP-SSW-102-22-F-D-VS_RCPT4-MFG 8652,497 r180 top
J24 "TFM-106-02-S-D-A" Samtec_TFM-106-02-x-D-A 2088.27,4802.6 r0 top
J25 "HSEC8-130-01-L-DV-A" controlCARD-180HSEC-60pinAddon 5730.34,639.74 r270 top
J26 "HSEC8-160-01-L-DV-A-BL" controlCARD-120HSEC 5729.47,2986.83 r270 top
J27 "SSW-103-22-F-D-VS-K" SAMTEC_SSW-103-22-F-D-VS-K 5270.28,1910.02 r0 top
J28 "SSW-102-22-F-D-VS" FP-SSW-102-22-F-D-VS_RCPT4-MFG 4520.28,1910.15 r0 top
J29 "SSW-103-22-F-D-VS-K" SAMTEC_SSW-103-22-F-D-VS-K 5260.99,2864.39 r0 top
J30 "SSW-102-22-F-D-VS" FP-SSW-102-22-F-D-VS_RCPT4-MFG 4510.99,2864.52 r0 top
J31 "SSW-103-22-F-D-VS-K" SAMTEC_SSW-103-22-F-D-VS-K 3481,4248 r0 top
J32 "SSW-102-22-F-D-VS" FP-SSW-102-22-F-D-VS_RCPT4-MFG 2731,4248.13 r0 top
J33 "1714984" Phoenix_1714984 556.27,4775.56 r180 top
J34 "851-43-008-10-001000" Mill-Max_851-43-008-10-001000 5387.63,616.44 r90 top
J35 "SSW-104-22-F-D-VS-K" FP-SSW-104-22-F-D-VS-K_HDR8-MFG 7822,4265.56 r0 top
J36 "SSW-103-22-F-D-VS-K" SAMTEC_SSW-103-22-F-D-VS-K 8722.01,4265.91 r0 top
J37 "1714955" Phoenix_1714955 4917,4666 r180 top
J38 "1714955" Phoenix_1714955 4356,4666 r180 top
K1 "FTR-K5AA012Y" FP-FTR-K5AA012Y_RELAY_PTH-MFG 2799.89,956.17 r180 top
L2 "SRN3015TA-2R2M" SRN3015TA 5500.27,4321.6 r270 top value=2.2uH
L3 "MPIA2510V2-4R7-R" FP-MPIA2510V2-4R7-R_1008-MFG#1 6316,3855 r180 top value=4.7uH
L4 "MPIA2510V2-4R7-R" FP-MPIA2510V2-4R7-R_1008-MFG#1 7007,3865 r90 top value=4.7uH
L5 "MPIA2510V2-4R7-R" FP-MPIA2510V2-4R7-R_1008-MFG#1 7573,187 r90 top value=4.7uH
L6 "MPIA2510V2-4R7-R" FP-MPIA2510V2-4R7-R_1008-MFG#1 7051,194 r90 top value=4.7uH
L7 "MPIA2510V2-4R7-R" FP-MPIA2510V2-4R7-R_1008-MFG#1 9910,3038 r270 top value=4.7uH
L8 "MPIA2510V2-4R7-R" FP-MPIA2510V2-4R7-R_1008-MFG#1 10225,3046 r180 top value=4.7uH
L9 "MPIA2510V2-4R7-R" FP-MPIA2510V2-4R7-R_1008-MFG#1 10598,1074 r0 top value=4.7uH
L10 "MPIA2510V2-4R7-R" FP-MPIA2510V2-4R7-R_1008-MFG#1 10021,1432 r180 top value=4.7uH
L11 "ACT45B-101-2P-TL003" ACT45B 3605.7,4733.6 r0 bottom value=100uH
L12 "MPIA2510V2-4R7-R" FP-MPIA2510V2-4R7-R_1008-MFG#2 4711.27,2306.6 r270 bottom value=4.7uH
L13 "MPIA2510V2-4R7-R" FP-MPIA2510V2-4R7-R_1008-MFG#2 4702.27,1766.6 r270 bottom value=4.7uH
L14 "MPIA2510V2-4R7-R" FP-MPIA2510V2-4R7-R_1008-MFG#2 4711.27,3307.97 r270 bottom value=4.7uH
L15 "MPIA2510V2-4R7-R" FP-MPIA2510V2-4R7-R_1008-MFG#2 4621.89,2967.35 r180 bottom value=4.7uH
L16 "FRM-DOC-15" FP-FRM-DOC-15_Common_Mode_Choke_1INCH90_1INCH9-MFG 949.27,2334.6 r0 top
L17 "FRM-DOC-15" FP-FRM-DOC-15_Common_Mode_Choke_1INCH90_1INCH9-MFG 953.27,645.6 r0 top
L18 "VI-20174A" FP-VI-20174A_RADIAL-MFG 3090.93,2510.6 r90 top
L19 "VI-20173B" FP-VI-20173B_PTH_INDUCTOR_34MM00_19MM00-MFG 6856,2193 r270 top value=50uH
LBL1 "THT-14-423-10" Label_650x200 9992.92,5071 r0 top
Logo1 "Texas Instruments" TI_Stacked_Overlay_Small 10083.81,4681 r0 top
Logo2 "FCC disclaimer" FCC_disclaimer 8799,4477 r0 top
Logo3 "WEEE logo" WEEE_Minimum 10820.28,5042 r0 top
Logo4 "CE Mark" CE_Mark_5mm 10781.87,4696.11 r0 top
LOGO5 "DANGER HIGH VOLTAGE" IEC_HighVoltage_Small 10921,2909 r270 top
LOGO6 "CAUTION HOT SURFACE" IEC_HotSurface_Small 10926,1113 r270 top
LOGO8 "CAUTION HOT SURFACE" IEC_HotSurface_Small 7956,4739 r0 top
LOGO9 "DANGER HIGH VOLTAGE" IEC_HighVoltage_Small 6891,4734 r0 top
MP1 "OBC_shield" 0-MFG 1010.09,2210.9 r0 top
Q1 "IPB80R290C3AATMA2" FP-IPB80R290C3AATMA2_D2PAK-MFG 6751.12,1210.03 r90 bottom
Q2 "IPB80R290C3AATMA2" FP-IPB80R290C3AATMA2_D2PAK-MFG 6327.27,1293.6 r270 bottom
Q3 "BSS806NEH6327XTSA1" SOT-23L 5504.27,4313.85 r0 bottom value=20V
Q4 "SQ1431EH-T1_GE3" FP-SQ1431EH-T1_GE3_SC-70-MFG 5659.27,4385.6 r90 bottom
Q5 "ZXMN7A11GTA" SOT-223 3563,935 r180 bottom value=70V
Q6 "NVHL025N65S3" FP-NVHL025N65S3_hm_TO-247-3-MFG 3520.37,1604.6 r90 bottom
Q7 "NVHL025N65S3" FP-NVHL025N65S3_hm_TO-247-3-MFG 2343.27,1604.6 r270 bottom
Q8 "NVHL025N65S3" FP-NVHL025N65S3_hm_TO-247-3-MFG 2343.27,3427.6 r270 bottom
Q9 "NVHL025N65S3" FP-NVHL025N65S3_hm_TO-247-3-MFG 3520.37,3427.6 r90 bottom
Q10 "2V7002KT1G" SOT-23 5344.6,2454.46 r180 top value=60V
R1 "WSL12066L000FEA18" 1206 10503.12,3697.32 r0 bottom value=0.006
R2 "WSL12066L000FEA18" 1206 10503.12,3802.89 r0 bottom value=0.006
